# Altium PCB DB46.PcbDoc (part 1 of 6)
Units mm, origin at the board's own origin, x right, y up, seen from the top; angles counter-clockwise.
Board outline 82.2 x 113.2 mm, 8 copper layers (Top Layer, MidLayer1, MidLayer2, GND, MidLayer3, VCC, MidLayer4, Bottom Layer), stack 1.576 mm thick; 186 components, 477 nets, 1727 pads, 1538 vias.
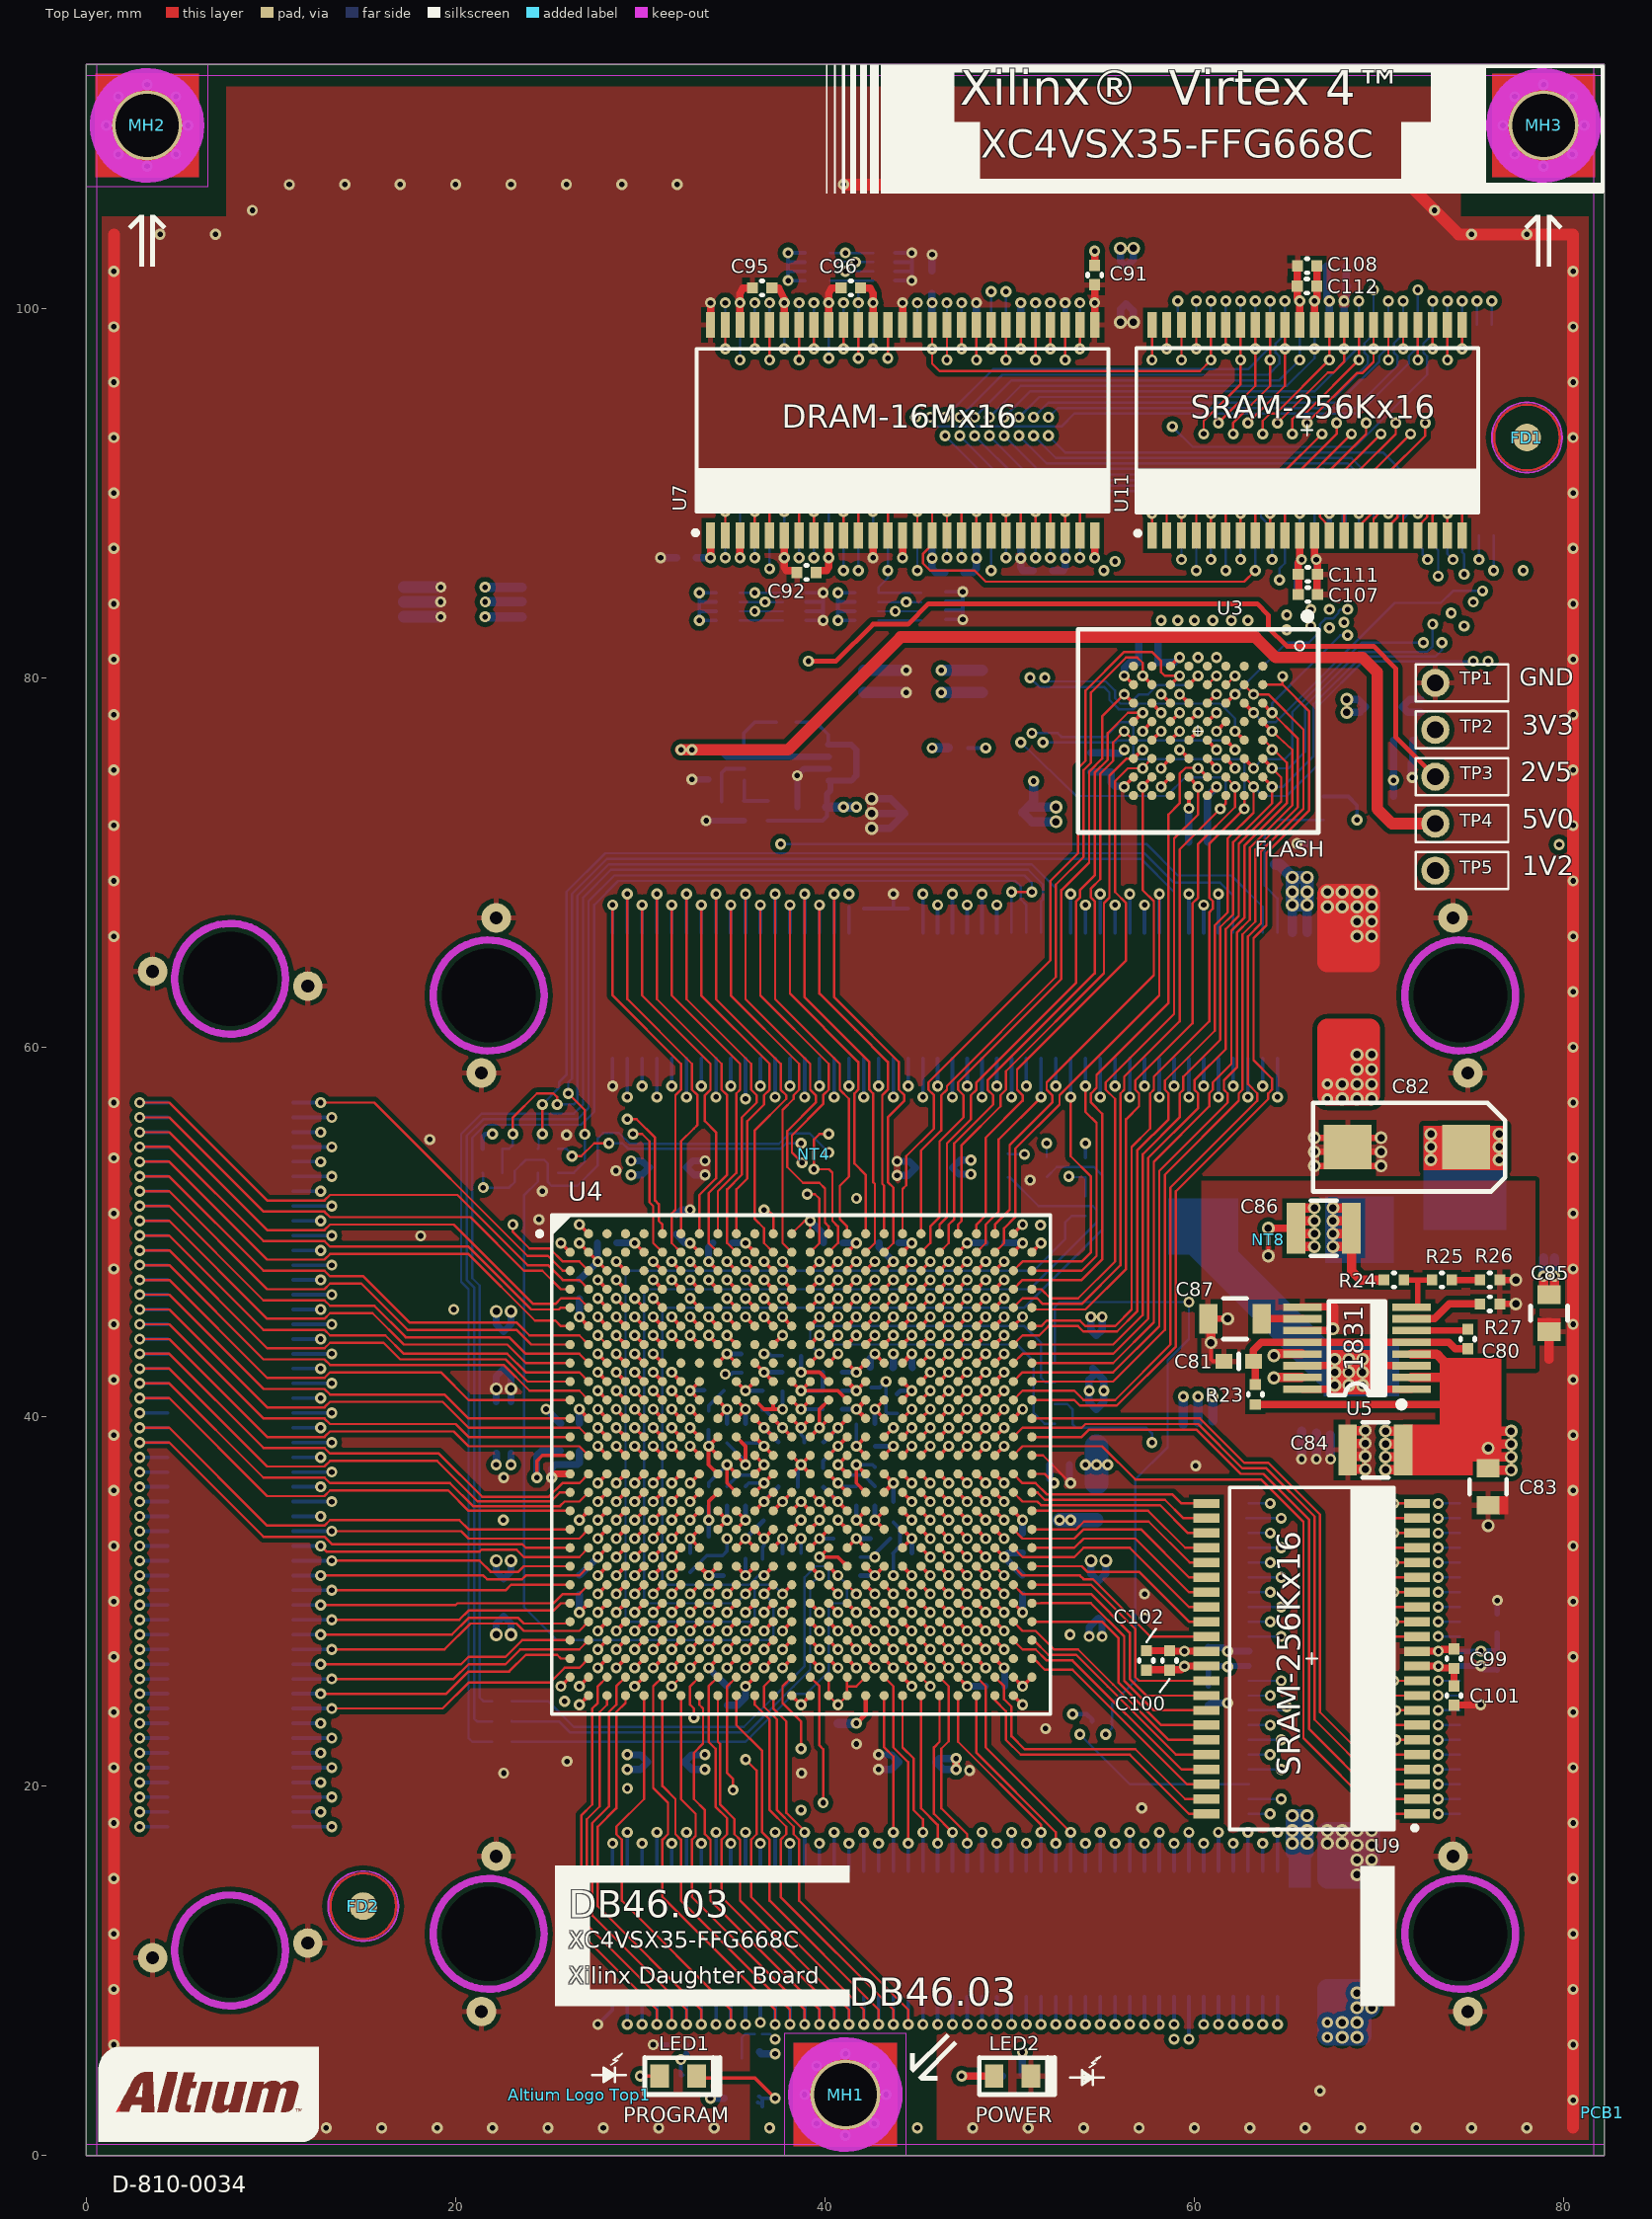
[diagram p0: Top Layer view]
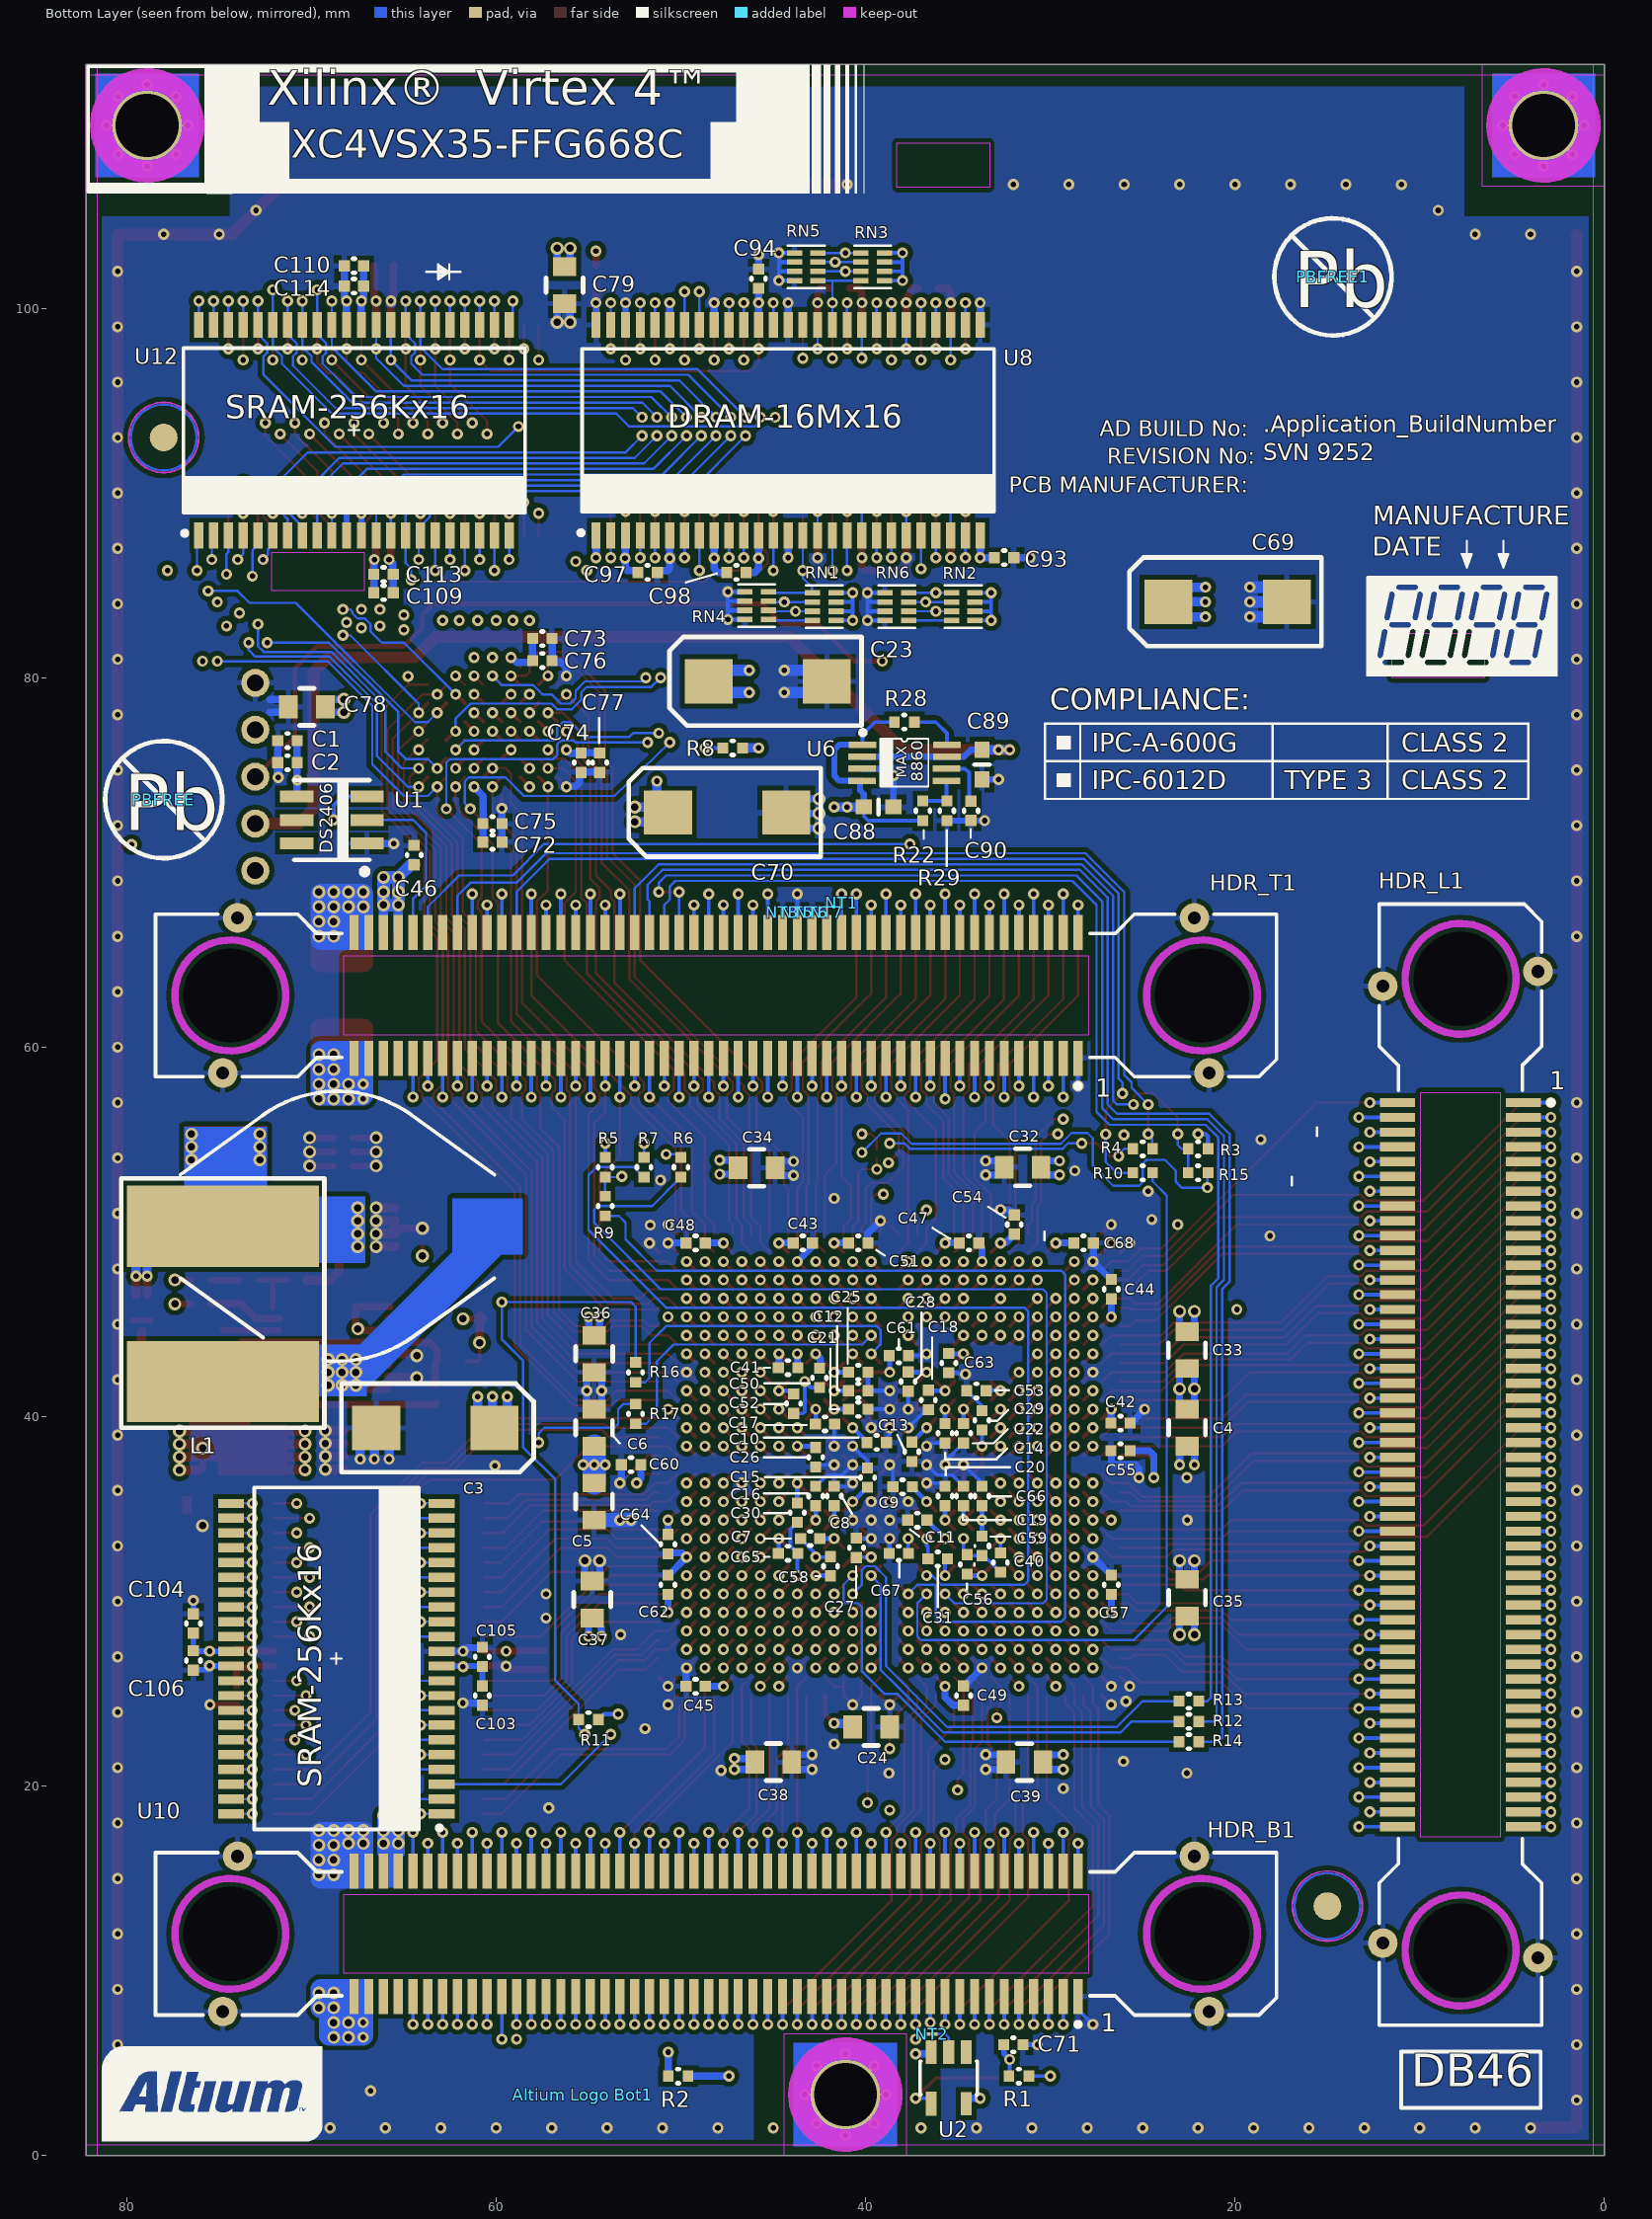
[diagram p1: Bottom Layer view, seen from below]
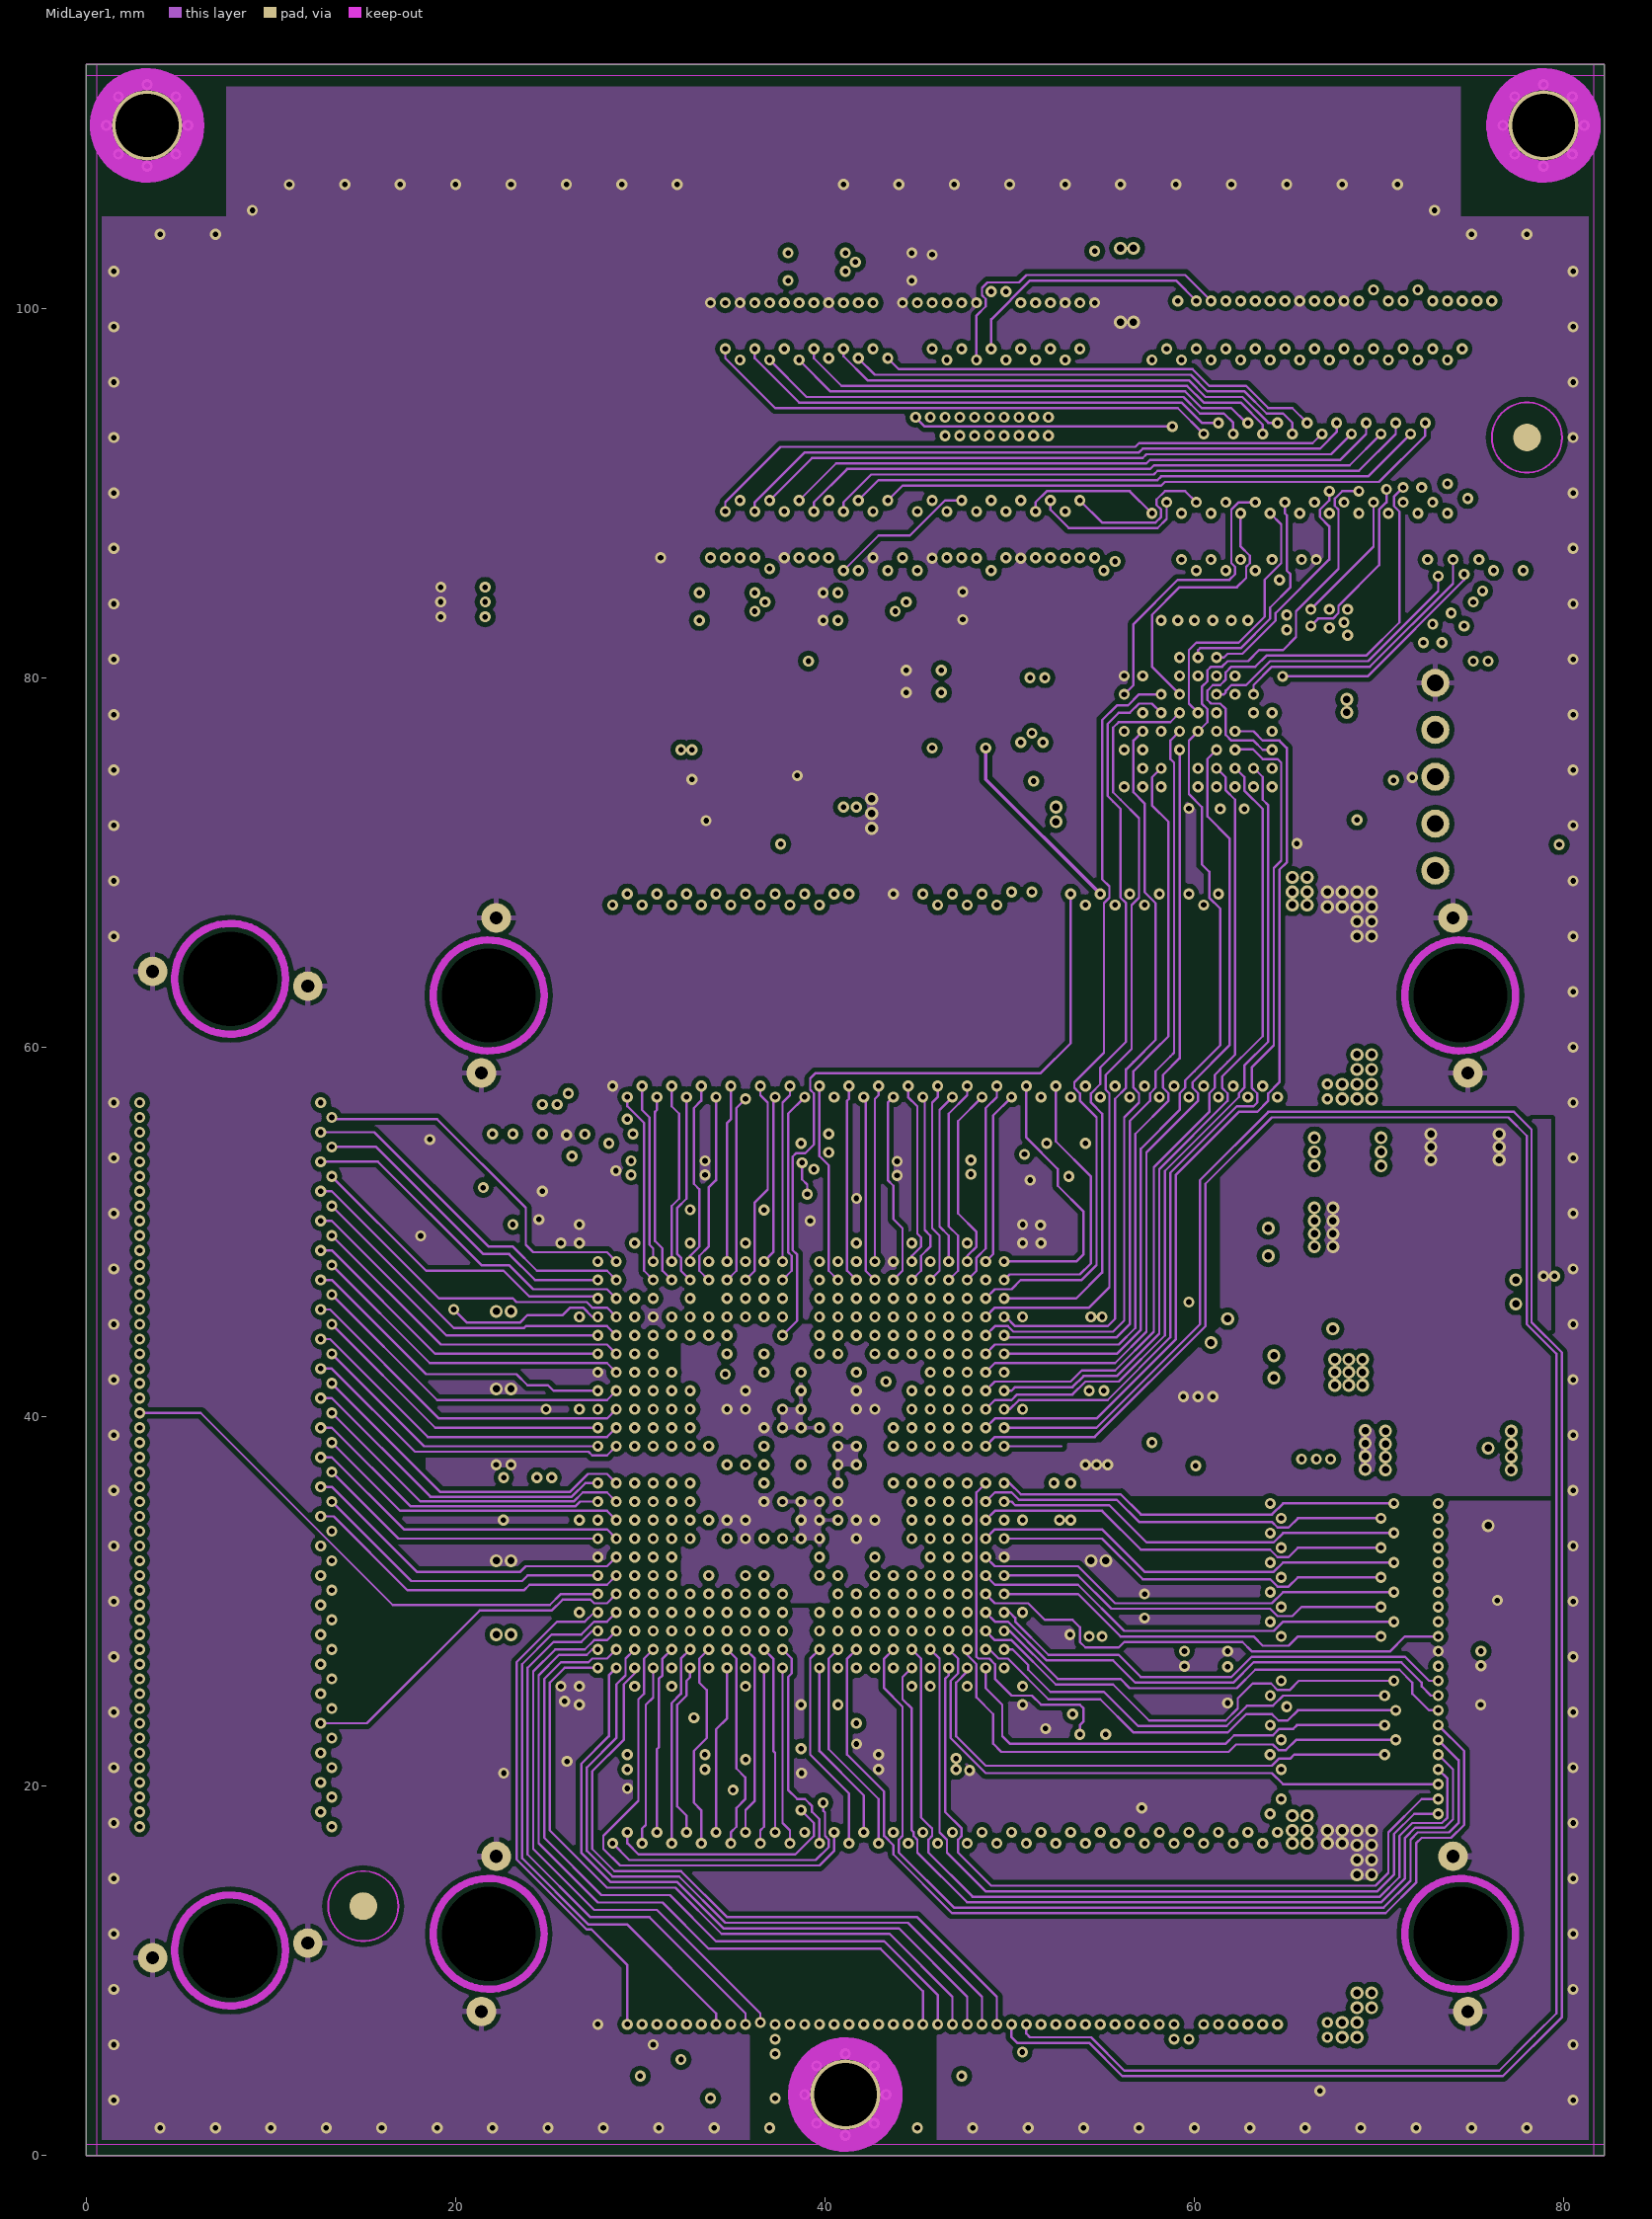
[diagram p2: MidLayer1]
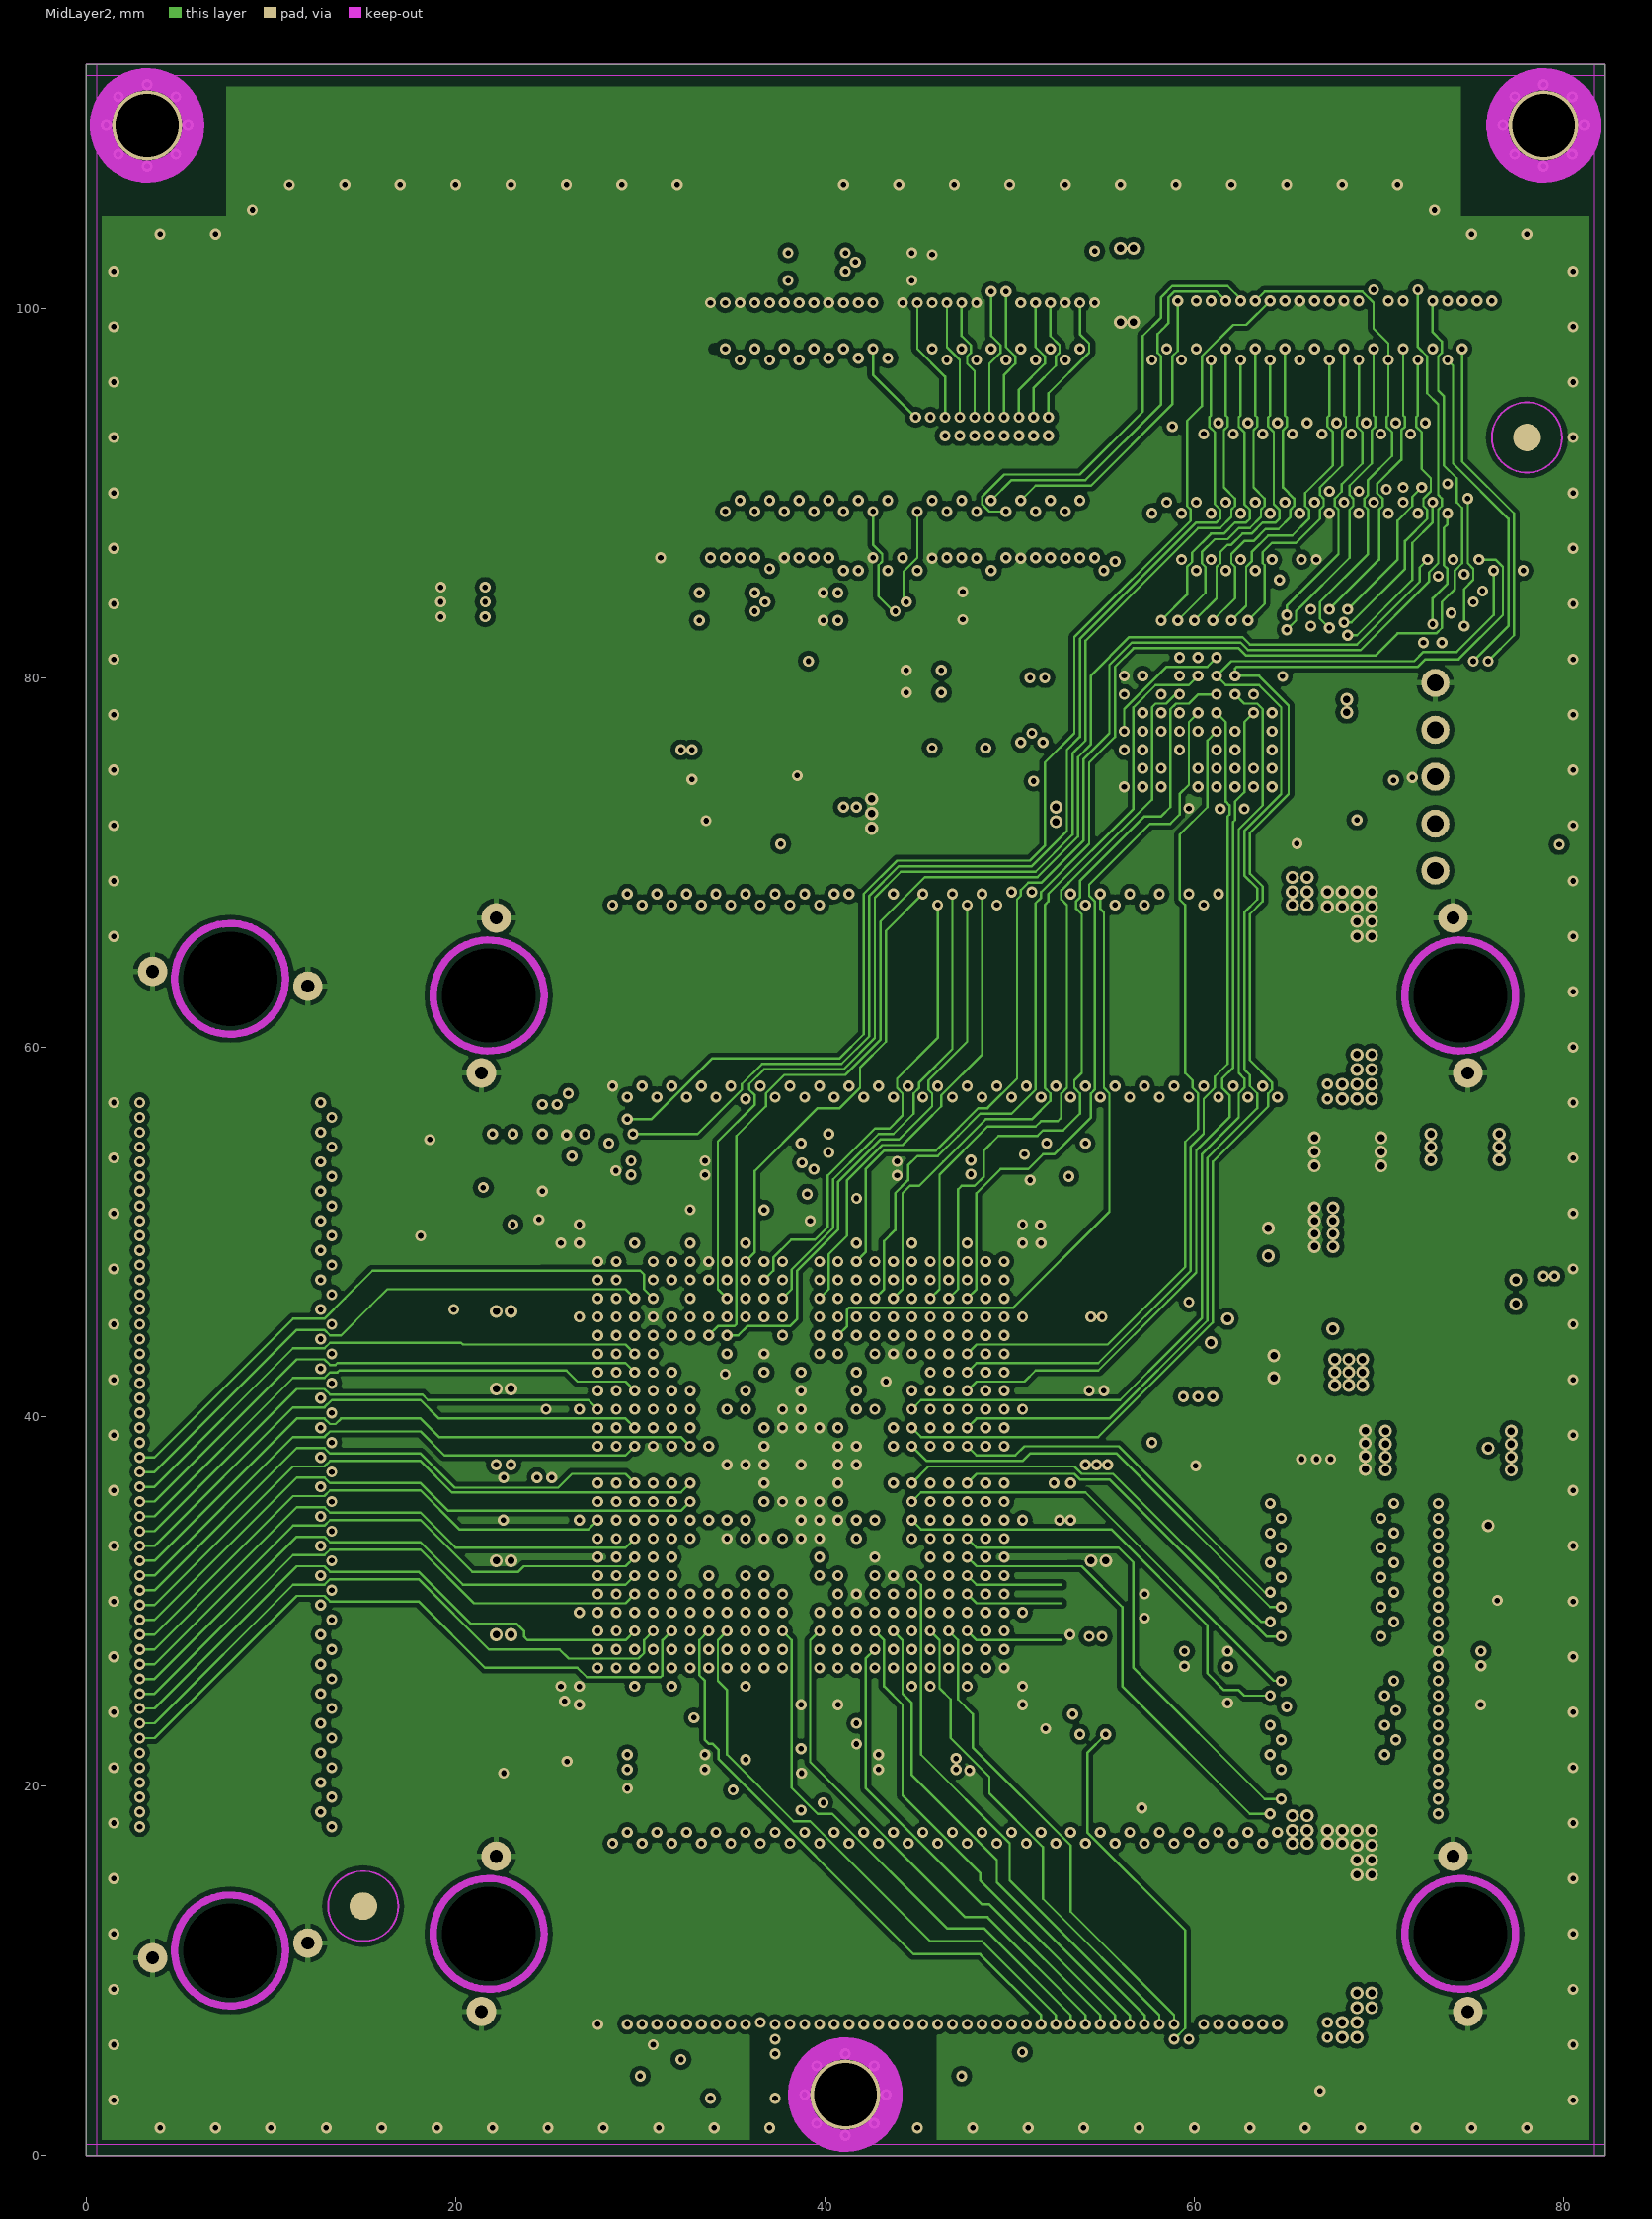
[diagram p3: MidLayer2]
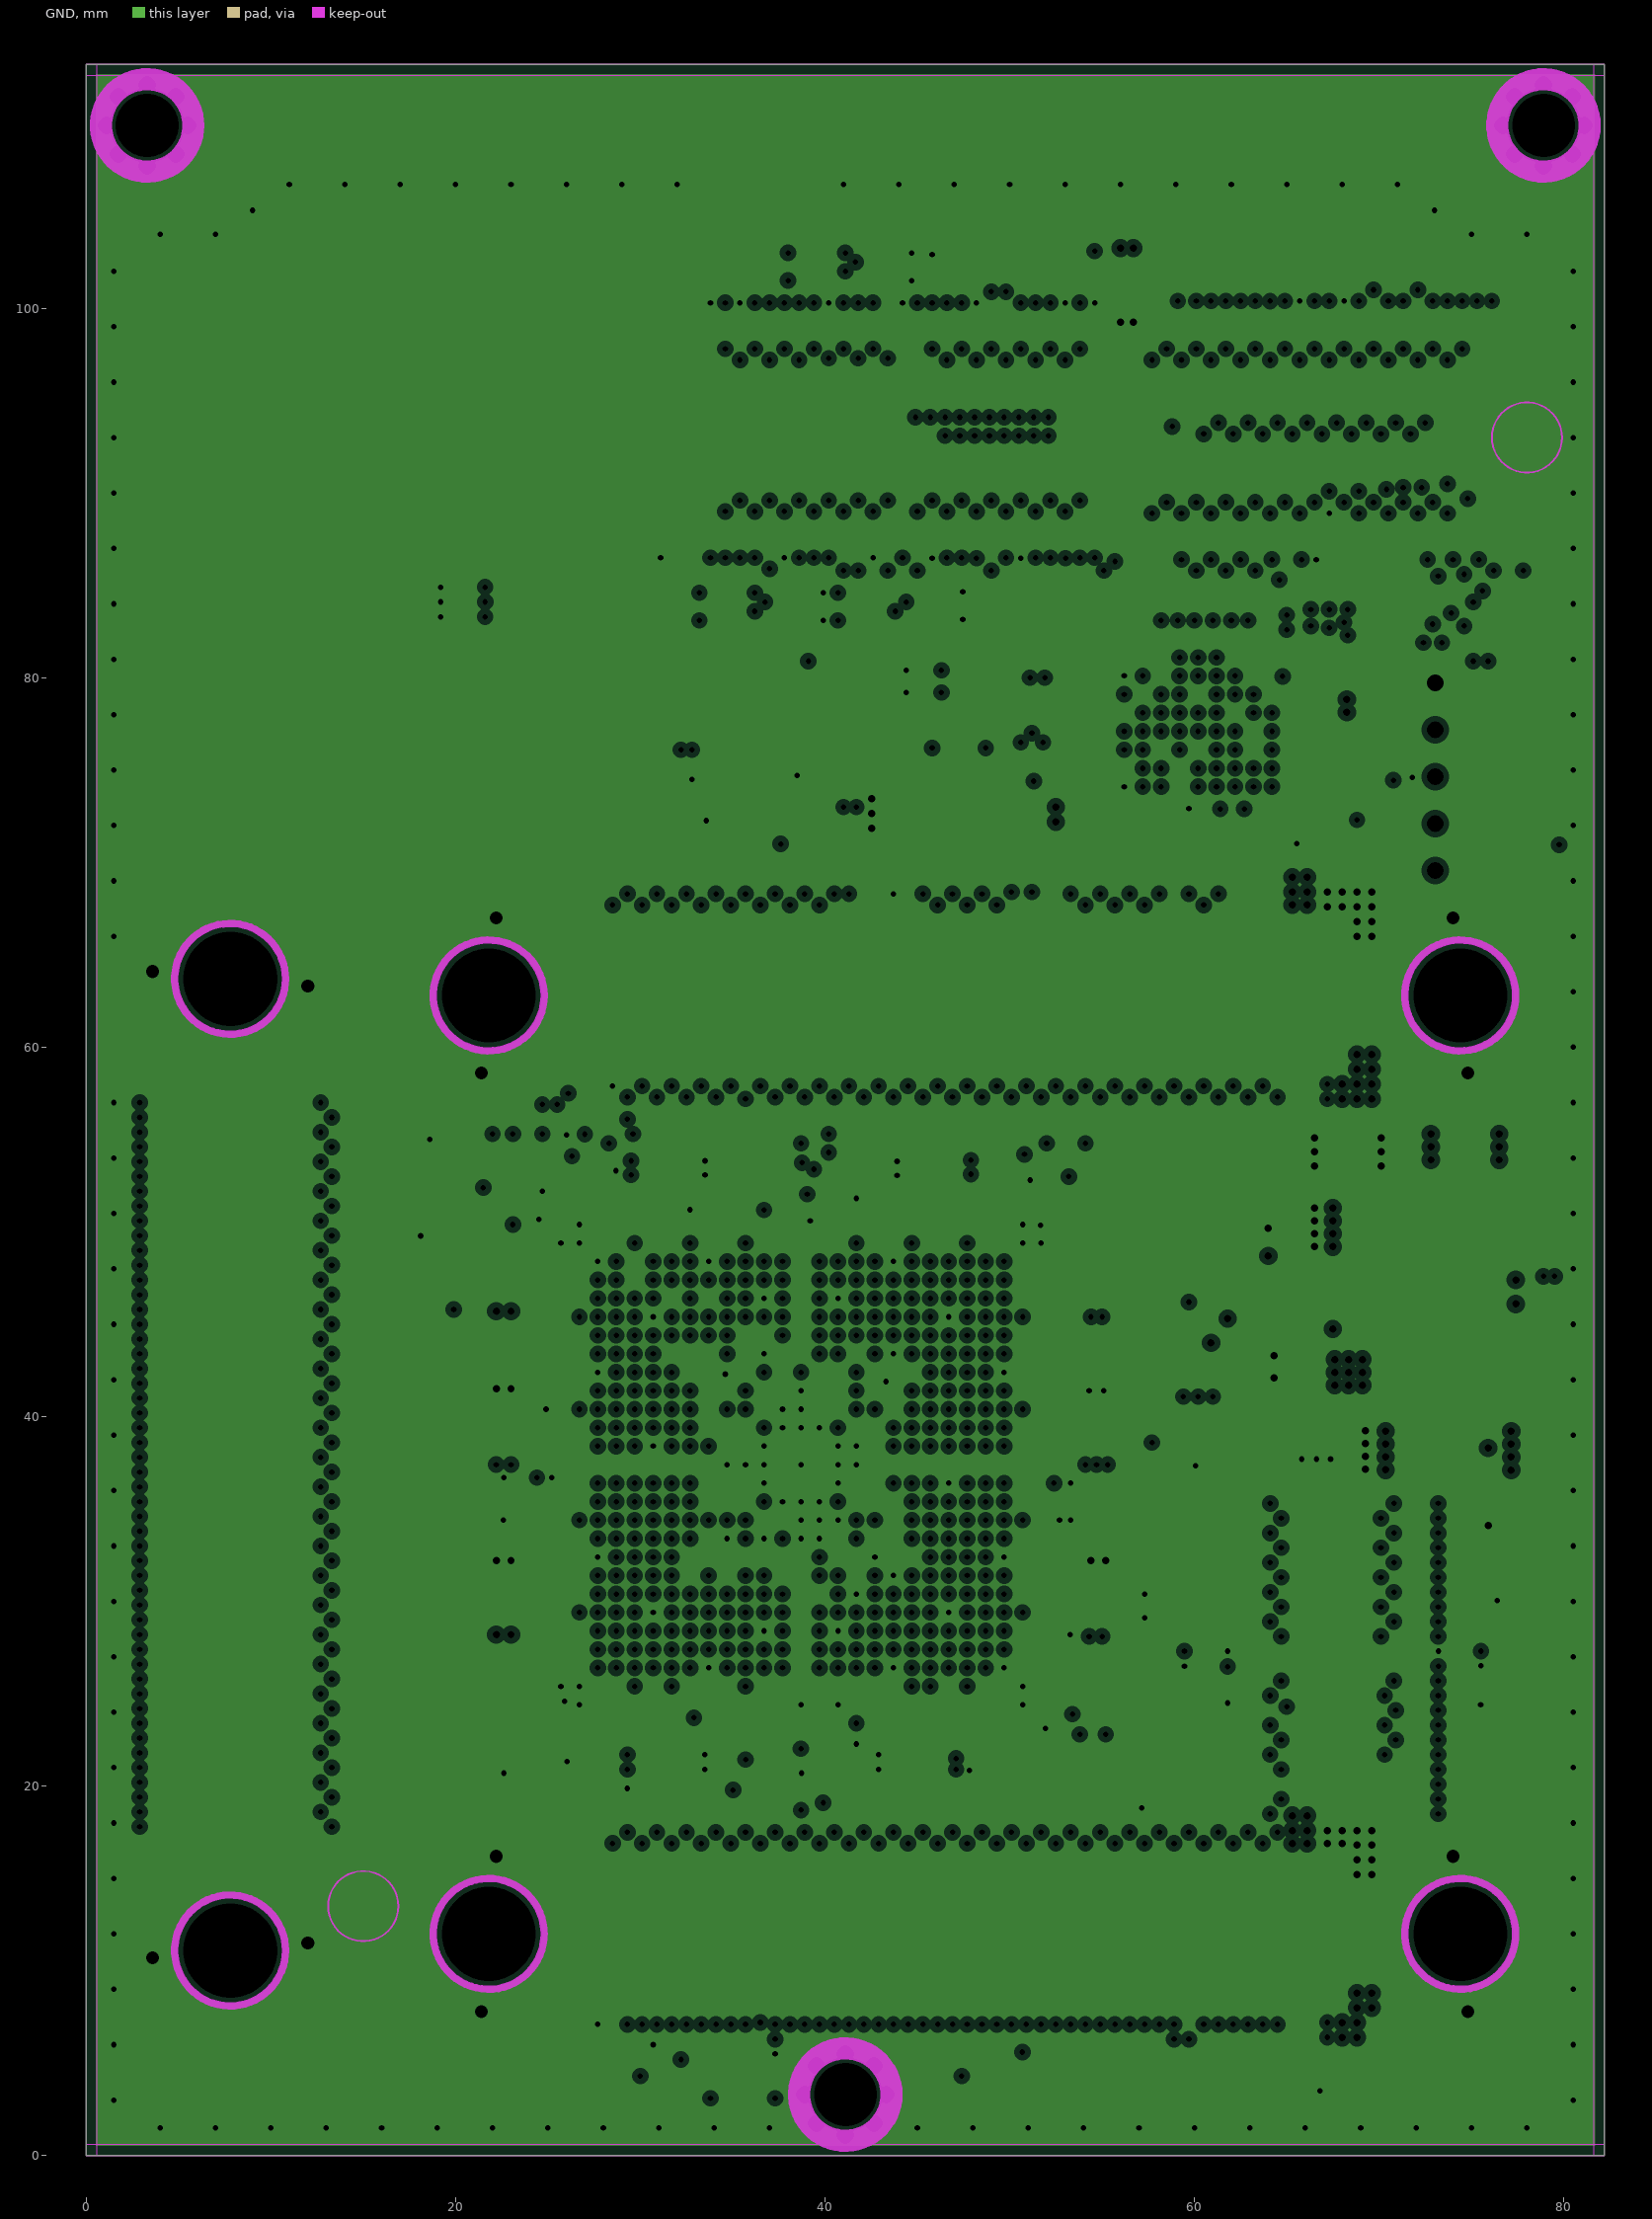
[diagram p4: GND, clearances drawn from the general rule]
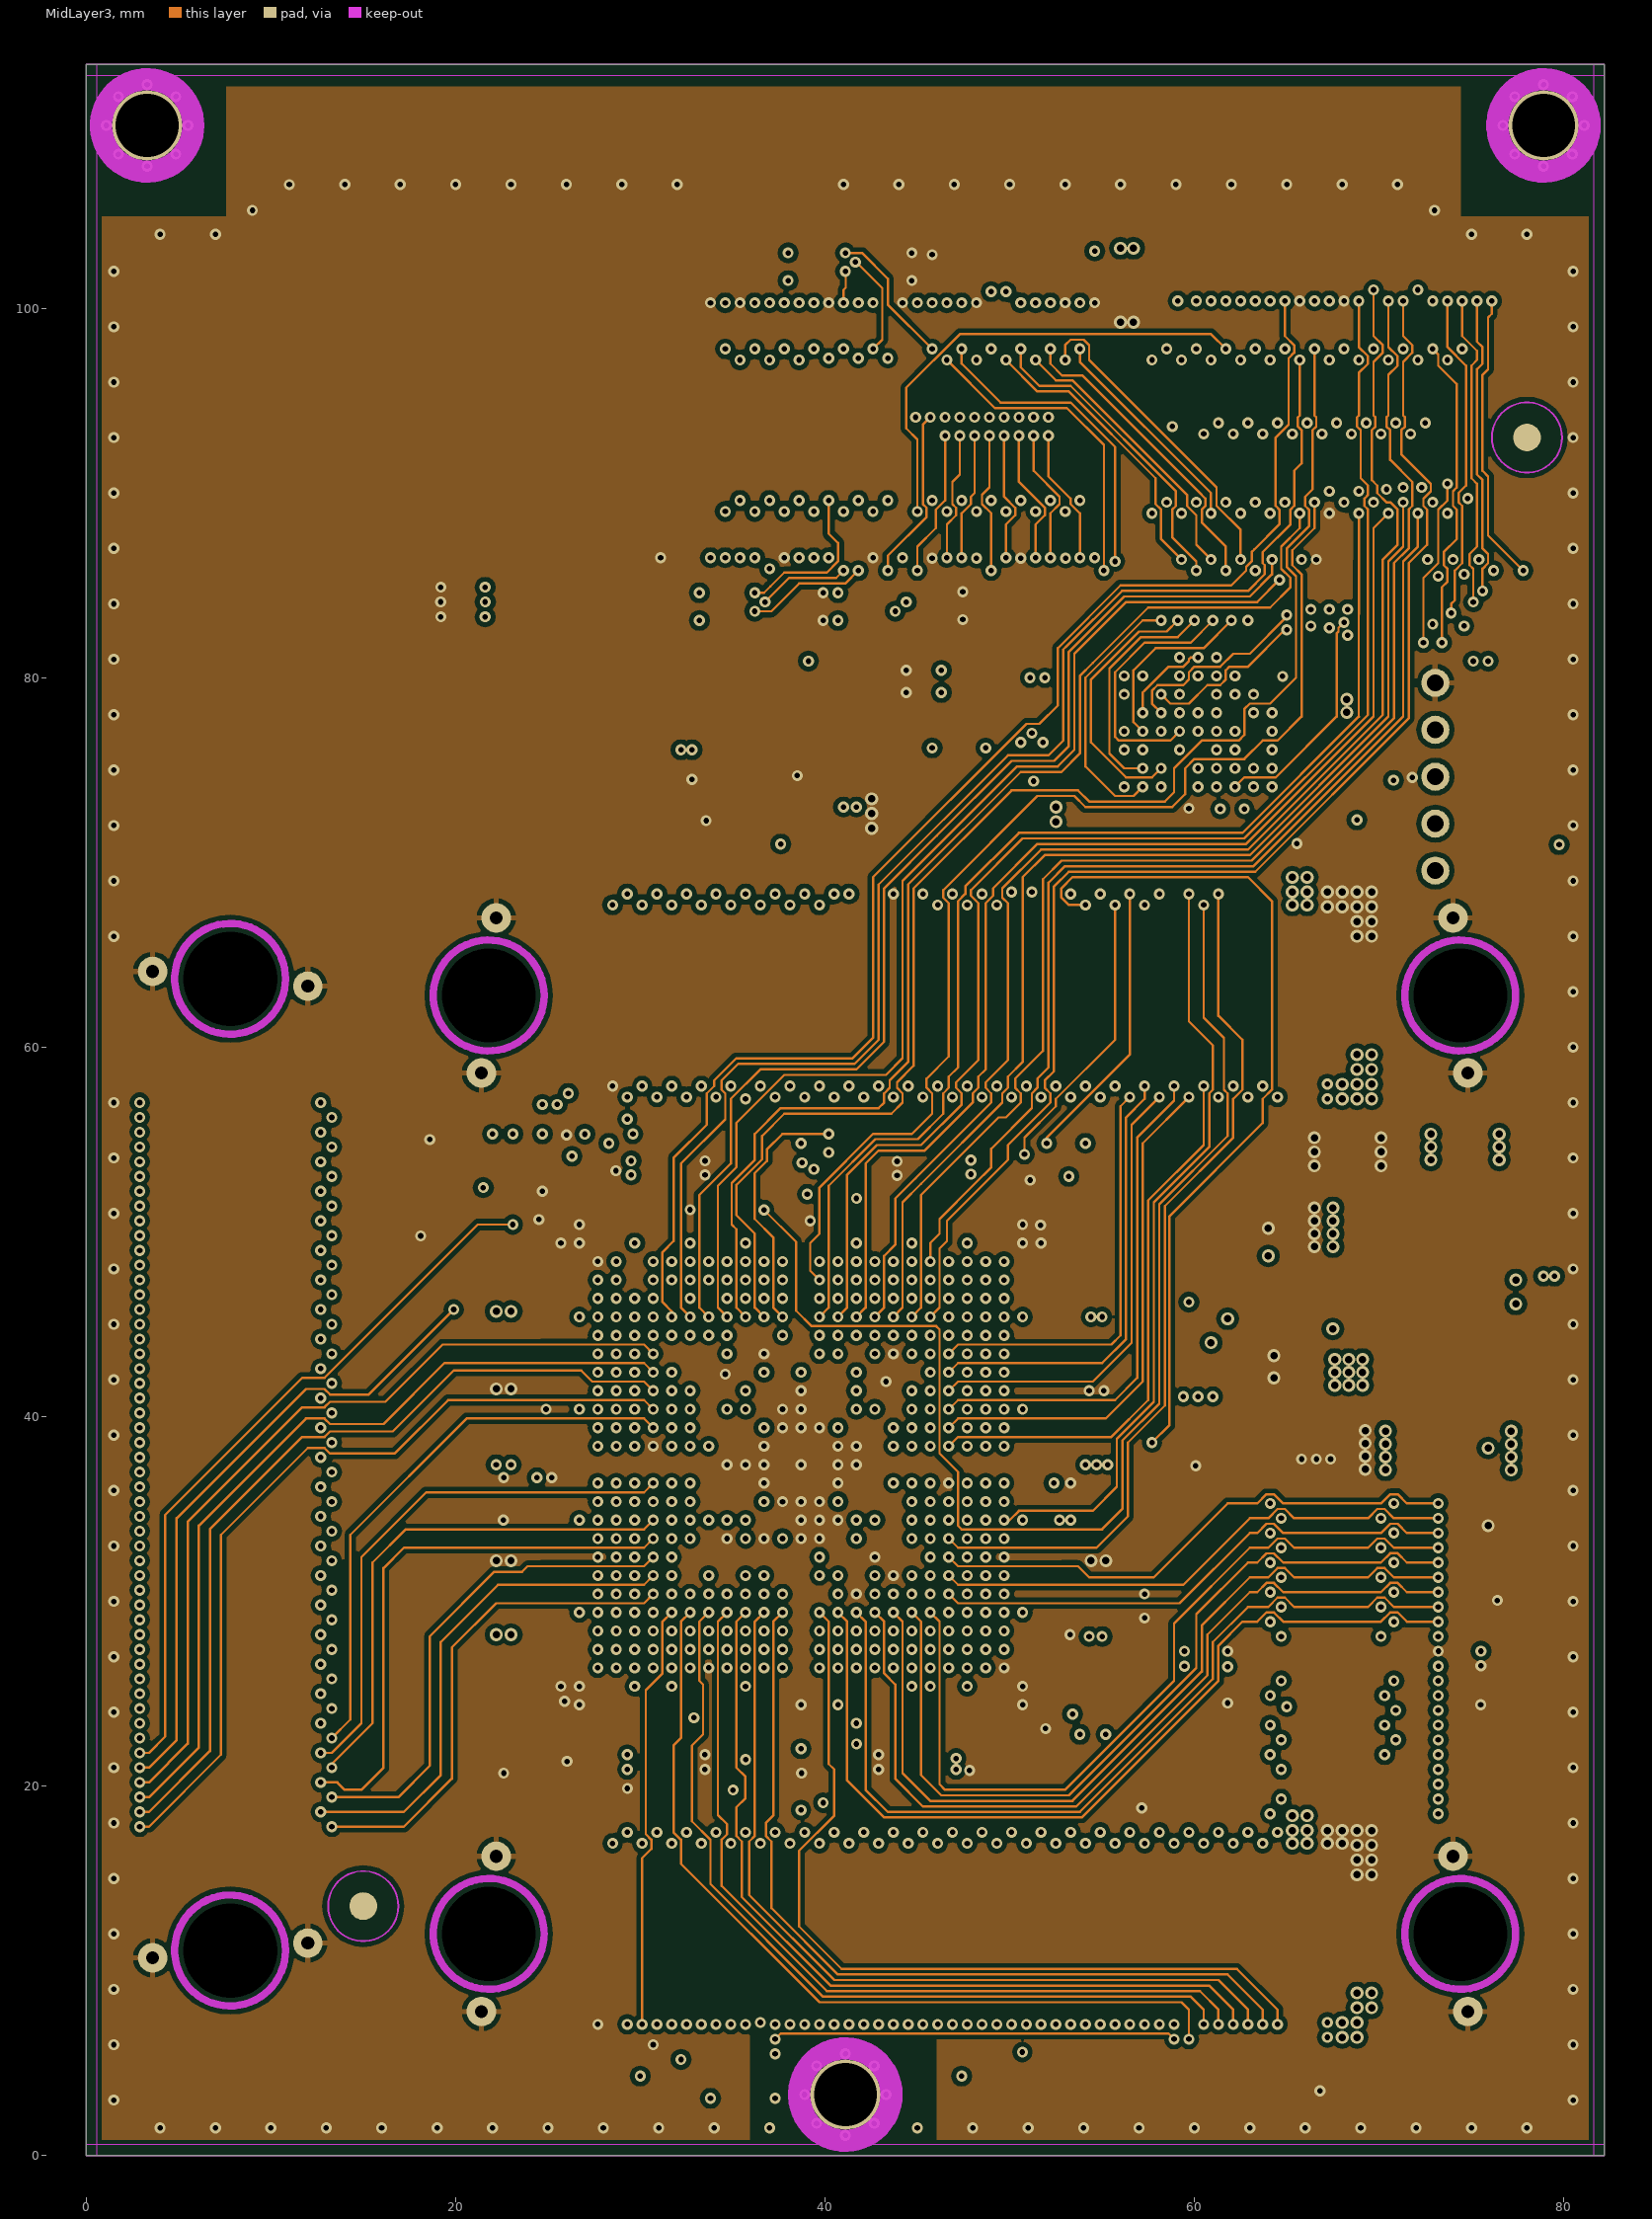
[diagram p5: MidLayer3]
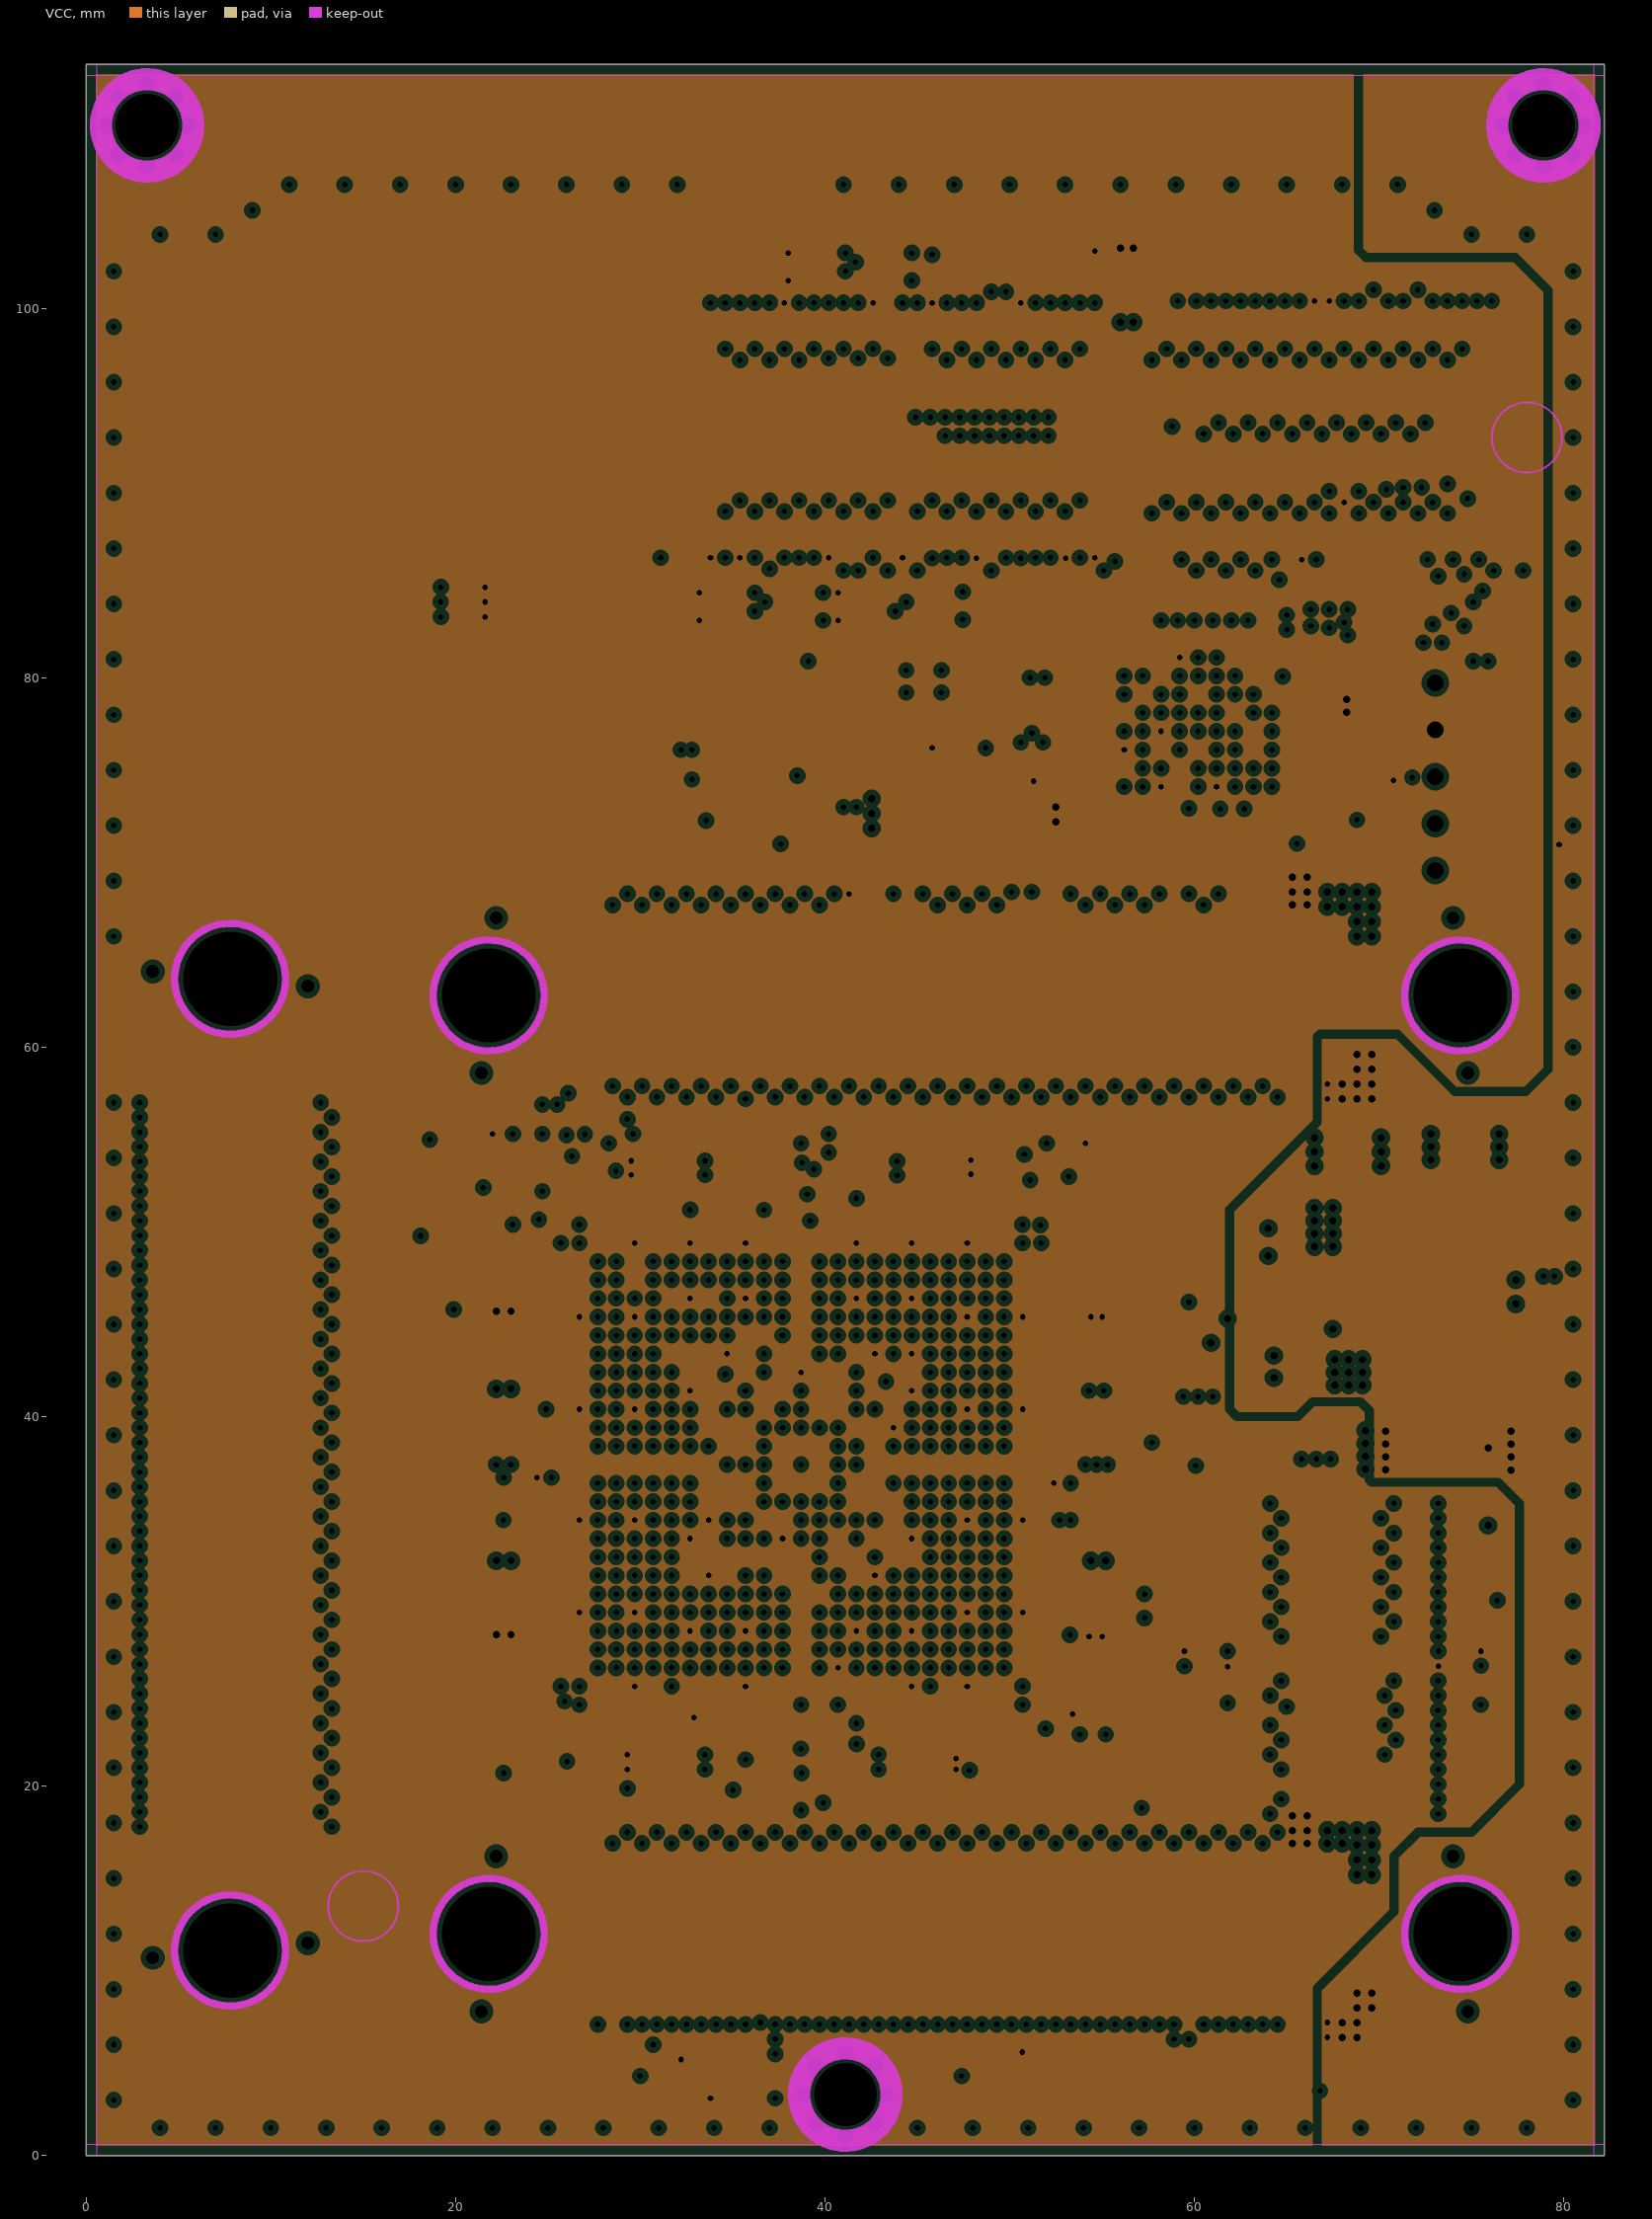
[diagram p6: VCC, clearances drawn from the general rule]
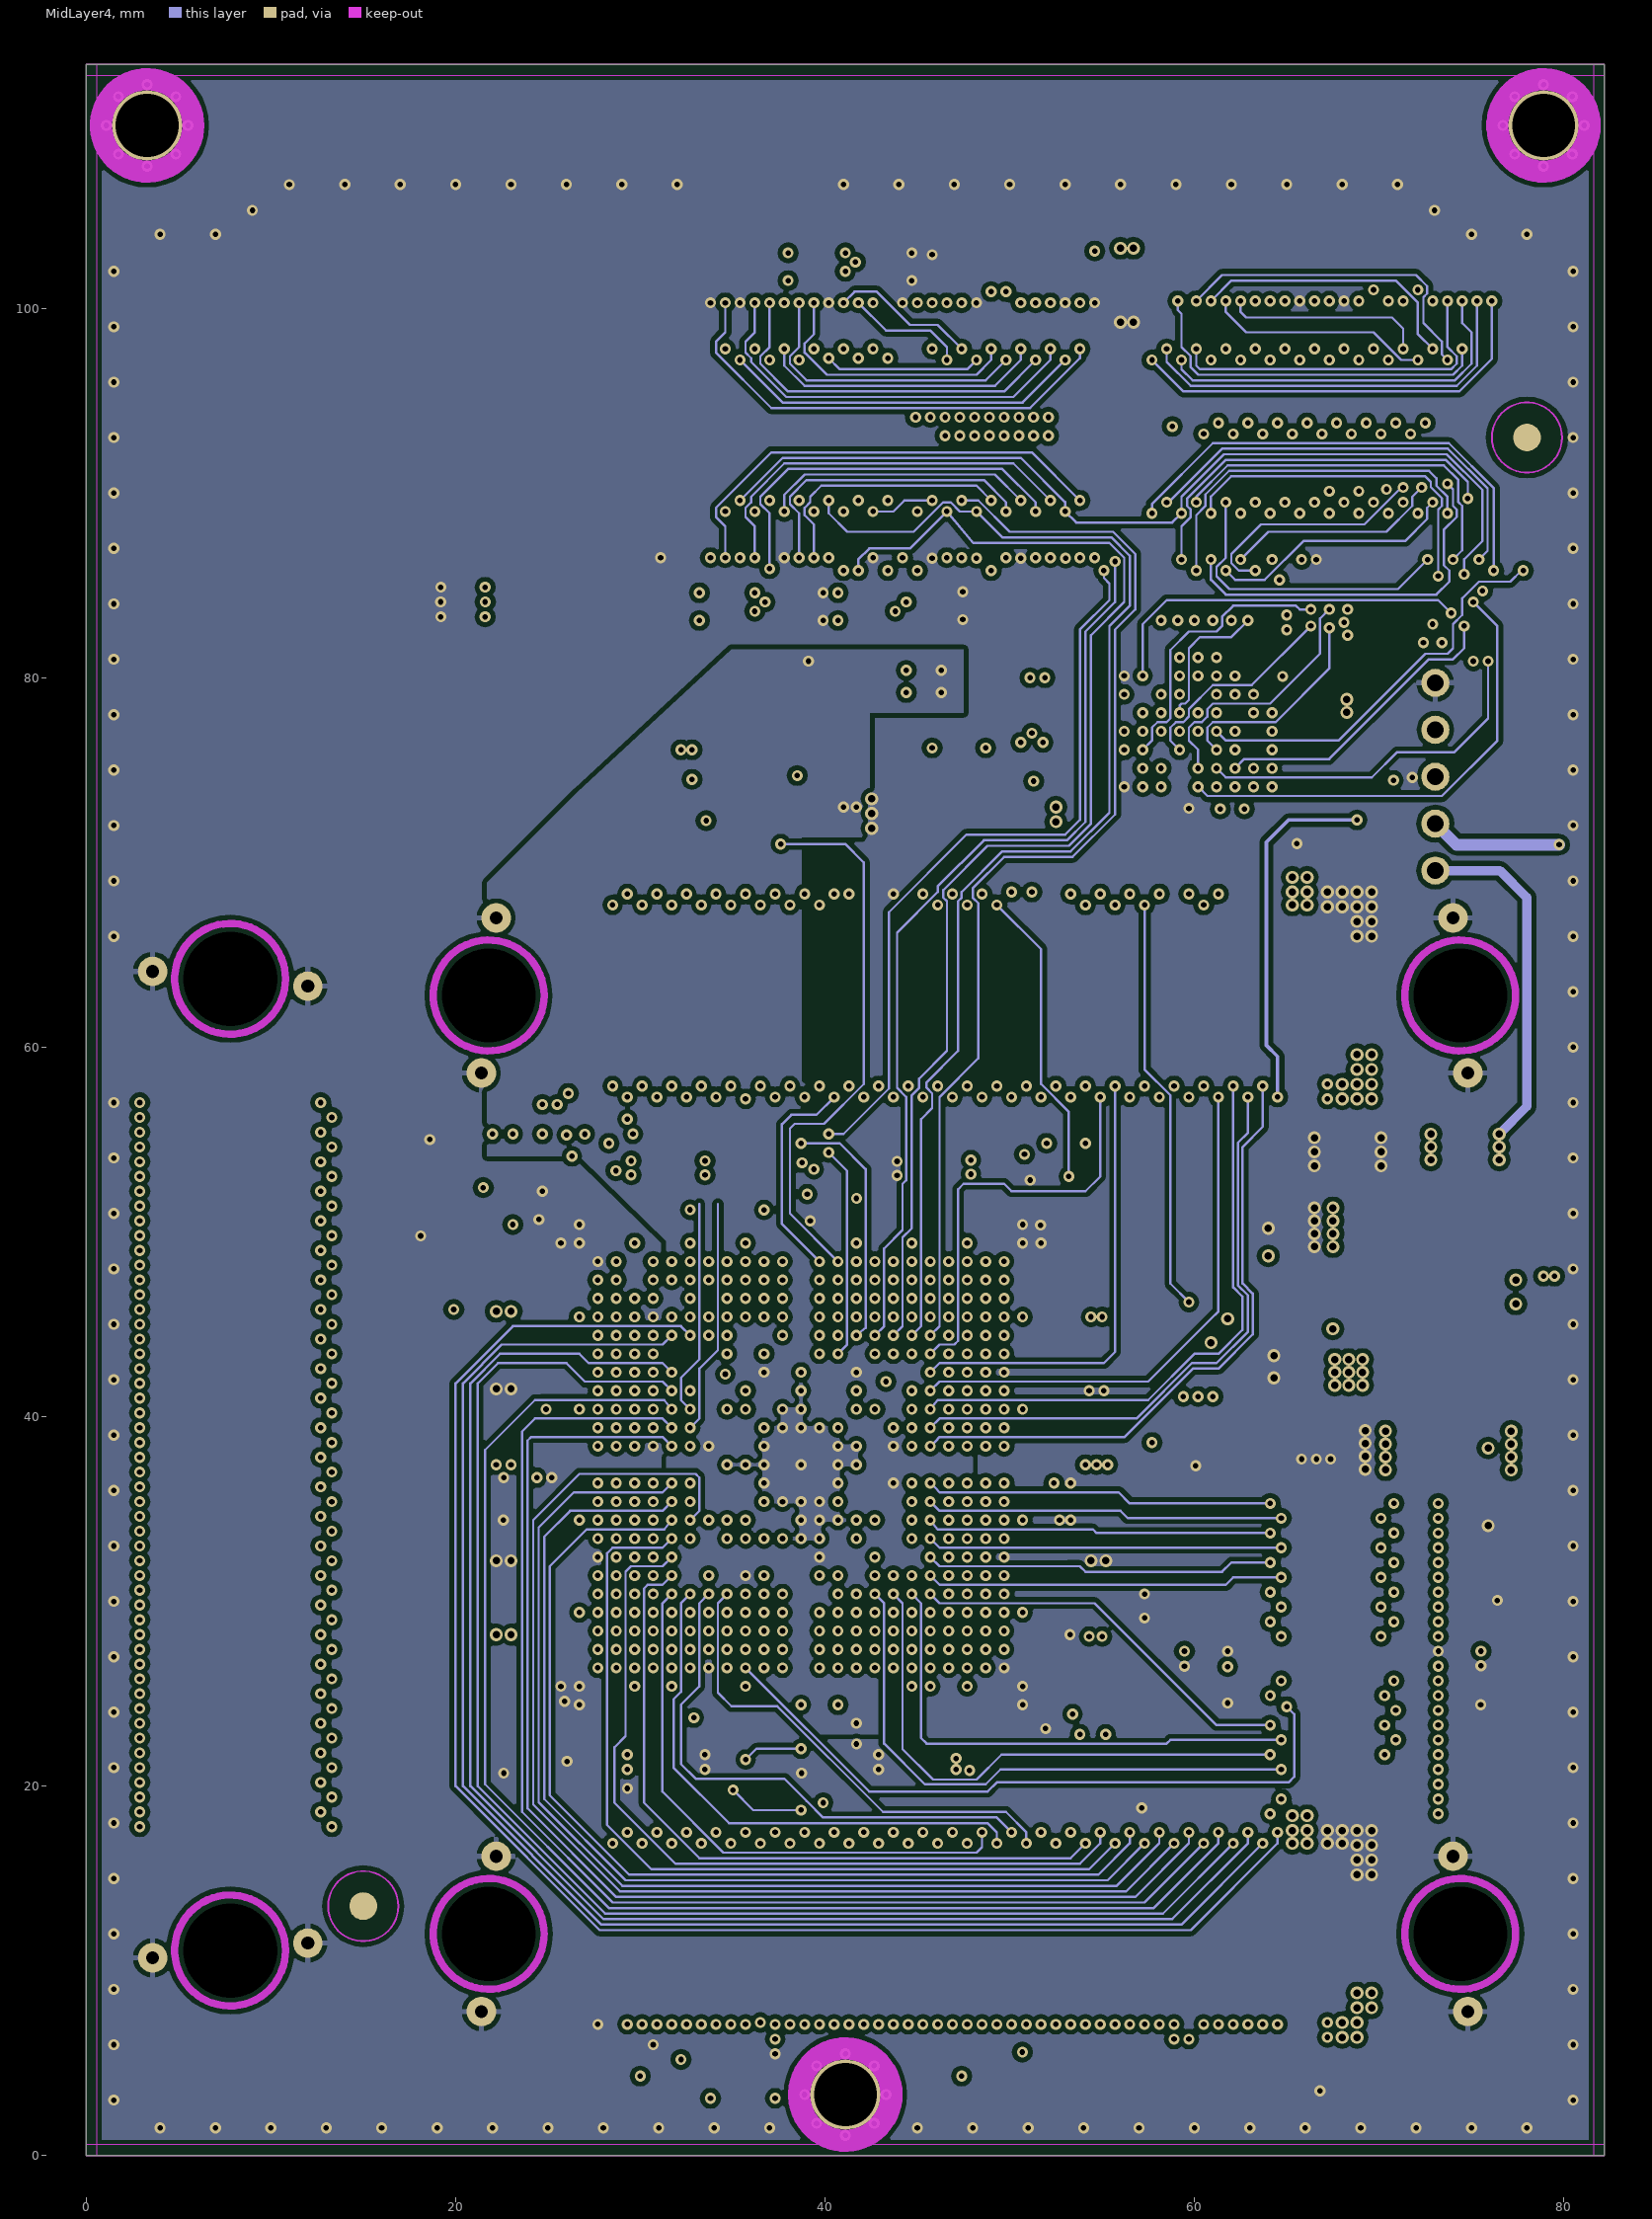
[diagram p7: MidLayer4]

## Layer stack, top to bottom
Top Layer: signal copper 0.0432
Dielectric: prepreg 0.127, FR-4, Dk 4.2
MidLayer1: signal copper 0.0356
Dielectric: core 0.254, FR-4, Dk 4.2
MidLayer2: signal copper 0.0356
Dielectric: prepreg 0.133, FR-4, Dk 4.2
GND: plane copper 0.036, net GND
Dielectric: core 0.254, FR-4, Dk 4.2
MidLayer3: signal copper 0.0356
Dielectric: prepreg 0.127, FR-4, Dk 4.2
VCC: plane copper 0.0356, net (Multiple Nets)
Dielectric: core 0.254, FR-4, Dk 4.2
MidLayer4: signal copper 0.0356
Dielectric: prepreg 0.127, FR-4, Dk 4.2
Bottom Layer: signal copper 0.0432

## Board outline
0,0 0,113.2 38.7,113.2 82.2,113.2 82.2,0

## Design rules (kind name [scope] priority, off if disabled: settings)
Clearance Clearance_Poly_Tight [InNamedPolygon('FPGAPWR-BL-1V2') Or InNamedPolygon('FPGAPWR-BL-3V3') Or InNamedPolygon('FPGAPWR-BL-2V5A') Or InNamedPolygon('FPGAPWR-BL-2V5B') Or InNamedPolygon('FPGAPWR-BL-2V5C') Or InNamedPolygon('FPGAPWR-BL-2V5D') Or InNamedPolygon('FPGAPWR-ML1-1V2') Or InNamedPolygon('FPGAPWR-BL-2V5E') Or InNamedPolygon('1V2-CONNECT-TO-L1-C17' ) Or InNamedPolygon('2V5') Or InNamedPolygon('LX') Or InNamedPolygon('2V5-TOP-CAP') Or InNamedPolygon('AGND-TOP')] p1: gap=0.127
Clearance Clearance_Polygon [InPolygon] p2: gap=0.254
Clearance "Pad-Pad Clearance Same Net" [IsPad vs IsPad] p3: gap=0.127
Clearance "General Clearance" [All] p4: gap=0.127
ComponentClearance [All] p1 off: gap=0.2 collisioncheckmode=3 verticalgap=0.254 showdistances=FALSE
DiffPairsRouting [All] p1 off: maxlimit=0.254 minlimit=0.254 mostfreqgap=0.254 maxuncoupledlength=12.7
FabricationTestPointUsage TestPointUsage [All] p1 off: valid=0 allowmultiple=FALSE
FabricationTestpoint Testpoint [All] p1 off: side=3 testpointundercomponent=TRUE minsize=1.016 maxsize=2.54 preferedsize=1.524 minholesize=0 maxholesize=1.016 preferedholesize=0.813 testpointgrid=0.025 allowsidetop=TRUE allowsidebottom=TRUE usegrid=TRUE gridtolerance=0
HoleSize [All] p1: absolutevalues=TRUE maxlimit=5.2 minlimit=0 maxpercent=80.000 minpercent=20.000
MatchedLengths DiffPair_MatchedLengths [(IsDifferentialPair And (Name = 'HDMI_D0')) Or (IsDifferentialPair And (Name = 'HDMI_D1')) Or (IsDifferentialPair And (Name = 'HDMI_D2')) Or (IsDifferentialPair And (Name = 'HDMI_CLK'))] p1: tolerance=25.4 checknetsindiffpair=TRUE checkdiffpairvsdiffpair=TRUE checkothers=TRUE
MatchedLengths DiffPair_MatchedLengths_1 [(IsDifferentialPair And (Name = 'DIFF_RX1'))] p2: tolerance=25.4 checknetsindiffpair=TRUE checkdiffpairvsdiffpair=TRUE checkothers=TRUE
MinimumAnnularRing MinimumAnnularRing_NonPlated [(ObjectKind = 'Pad') And (HoleDiameter >= '0.7') And (PadIsPlated = 'False')] p1: minimumring=-5
MinimumAnnularRing [All] p2: minimumring=0.15
MinimumSolderMaskSliver [All] p1: minsoldermaskwidth=0.102
PlaneClearance [All] p1: clearance=0.3
PlaneConnect [All] p1: planeconnectstyle=Direct reliefexpansion=0.5 reliefentries=4 reliefconductorwidth=0.25 reliefairgap=0.25
PolygonConnect PolygonConnect_Via [IsVia] p1: connectstyle=Direct reliefconductorwidth=0.254 reliefentries=4 polygonreliefangle="90 Angle"
PolygonConnect "PolygonConnect - Heatsink" [(HasFootprint('TO-263') AND InNet('VCCINT'))] p2: connectstyle=Direct reliefconductorwidth=0.254 reliefentries=4 polygonreliefangle="90 Angle"
PolygonConnect [All] p3: connectstyle=Relief reliefconductorwidth=0.3 reliefentries=4 polygonreliefangle="90 Angle"
RoutingLayers [All] p1: top layer_v5=FALSE mid layer 1_v5=FALSE mid layer 2_v5=FALSE mid layer 3_v5=FALSE mid layer 4_v5=FALSE bottom layer_v5=FALSE
RoutingVias [All] p1: holewidth=0.3 width=0.6 viastyle="Through Hole" minholewidth=0.3 minwidth=0.6 maxholewidth=0.5 maxwidth=0.9
ShortCircuit ShortCircuit_1 [Net = 'No Net' vs Net = 'No Net'] p1: allowed=TRUE
ShortCircuit [All] p2: allowed=FALSE
SilkToSilkClearance SilkToSilkClearance_InvToFill [(ObjectKind = 'Text') And (TextKind <> 'Stroke Font') vs isFill] p1: silktosilkclearance=0
SilkToSilkClearance SilkToSilkClearance_Labels [(ObjectKind = 'Text') And (TextKind <> 'Stroke Font') vs (ObjectKind = 'Text') And (TextKind <> 'Stroke Font')] p2: silktosilkclearance=0
SilkToSilkClearance SilkToSilkClearance_Pb [(ObjectKind = 'Text') And (StringText = 'Pb') vs istrack and onsilkscreen] p3: silktosilkclearance=0
SilkToSilkClearance [All] p4: silktosilkclearance=0.127
SilkscreenOverComponentPads [All] p1: minsilkscreentomaskgap=0.051
SolderMaskExpansion SolderMaskExpansion_Vias [IsVia] p1: expansion=-0.65
SolderMaskExpansion [All] p2: expansion=0.038
Width [All] p1: maxlimit=2.5 minlimit=0.127 preferedwidth=0.127
16 further rules are at their usual default settings.

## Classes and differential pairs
component class U_DB46_Hardware_Kit: FD1 FD2 PCB1
channel class SRAM_256Kx16_TSOP44: U_SRAM_K6R4016V1D-TC10T_256Kx161 U_SRAM_K6R4016V1D-TC10T_256Kx162
component class COM_SRAM: C107 C108 C109 C110 C111 C112 C113 C114 U11 U12
component class U_FPGA: C78 C79 NT2 NT3 NT4 NT5 NT6 NT7 R3 R4 R5 R6 R7 R8 R9 R10 R11 R12 R13 R14 R15 R16 R17 U4
component class COM_SDRAM: C91 C92 C93 C94 C95 C96 C97 C98 U7 U8
component class U_CommonMemory_Termination: RN1 RN2 RN3 RN4 RN5 RN6
component class COM_FLASH: C72 C73 C74 C75 C76 C77 U3
component class U_MOUNTS: "Altium Logo Bot1" "Altium Logo Top1" LB1 LB2 LB3 MH1 MH2 MH3 PCBA1
net class PWRNET: 1V2 2V5 3V3 5V0 AGND
differential pair class DIFF_OUT: DIFF_TX0 DIFF_TX1 DIFF_TX2 DIFF_TX3
differential pair class DIFF_IN: DIFF_RX0 DIFF_RX1 DIFF_RX2 DIFF_RX3
net class SW[4..0]: SW0 SW1 SW2 SW3 SW4
net class LED[7..0]: LED0 LED1 LED2 LED3 LED4 LED5 LED6 LED7
net class IO[35..0]: IO0 IO1 IO2 IO3 IO4 IO5 IO6 IO7 IO8 IO9 IO10 IO11 IO12 IO13 IO14 IO15 IO16 IO17 IO18 IO19 IO20 IO21 IO22 IO23 IO24 IO25 IO26 IO27 IO28 IO29 IO30 IO31 IO32 IO33 IO34 IO35
net class FPGA_M[2..0]: FPGA_M0 FPGA_M1 FPGA_M2
net class FPGA_ID[3..0]: FPGA_ID0 FPGA_ID1 FPGA_ID2 FPGA_ID3
net class DIP[7..0]: DIP0 DIP1 DIP2 DIP3 DIP4 DIP5 DIP6 DIP7
net class BUS_NBE[3..0]: BUS_NBE0 BUS_NBE1 BUS_NBE2 BUS_NBE3
net class BUS_D[31..0]: BUS_D0 BUS_D1 BUS_D2 BUS_D3 BUS_D4 BUS_D5 BUS_D6 BUS_D7 BUS_D8 BUS_D9 BUS_D10 BUS_D11 BUS_D12 BUS_D13 BUS_D14 BUS_D15 BUS_D16 BUS_D17 BUS_D18 BUS_D19 BUS_D20 BUS_D21 BUS_D22 BUS_D23 BUS_D24 BUS_D25 BUS_D26 BUS_D27 BUS_D28 BUS_D29 BUS_D30 BUS_D31
component class U_MotherBoardConnectors: HDR_B1 HDR_L HDR_L1 HDR_T1 NT1
component class U_Bypass_1V2: C3 C4 C5 C6 C7 C8 C9 C10 C11 C12 C13 C14 C15 C16 C17 C18 C19 C20 C21 C22
component class U_Bypass_3V3: C32 C33 C34 C35 C36 C37 C38 C39 C40 C41 C42 C43 C44 C45 C46 C46_FP C47 C47_FP C48 C48_FP C49 C49_FP C50 C51 C51_FP C52 C52_FP C53 C54 C55 C56 C56_FP C57 C58 C58_FP C59 C59_FP C60 C60_FP C61 C61_FP C62 C63 C64 C65 C65_FP C66 C67 C68 C69_FP C71_FP C72_FP C73_FP C79_FP C81_FP C82_FP C88_FP C90_FP C91_FP C93_FP C95_FP C96_FP C97_FP C98_FP C101_FP C102_FP C103_FP C104_FP C105_FP C106_FP
component class U_Bypass_Board: C1_PSU C4_MB C6_MB C69 C70
net class DAU_TFT_BLUE[4..0]: DAU_TFT_BLUE0 DAU_TFT_BLUE1 DAU_TFT_BLUE2 DAU_TFT_BLUE3 DAU_TFT_BLUE4
net class DAU_TFT_CL[3..1]: DAU_TFT_CL1 DAU_TFT_CL2 DAU_TFT_CL3
net class DAU_TFT_GREEN[5..0]: DAU_TFT_GREEN0 DAU_TFT_GREEN1 DAU_TFT_GREEN2 DAU_TFT_GREEN3 DAU_TFT_GREEN4 DAU_TFT_GREEN5
net class DAU_TFT_RED[4..0]: DAU_TFT_RED0 DAU_TFT_RED1 DAU_TFT_RED2 DAU_TFT_RED3 DAU_TFT_RED4
net class EXTEND_A[49..0]: EXTEND_A0 EXTEND_A1 EXTEND_A2 EXTEND_A3 EXTEND_A4 EXTEND_A5 EXTEND_A6 EXTEND_A7 EXTEND_A8 EXTEND_A9 EXTEND_A10 EXTEND_A11 EXTEND_A12 EXTEND_A13 EXTEND_A14 EXTEND_A15 EXTEND_A16 EXTEND_A17 EXTEND_A18 EXTEND_A19 EXTEND_A20 EXTEND_A21 EXTEND_A22 EXTEND_A23 EXTEND_A24 EXTEND_A25 EXTEND_A26 EXTEND_A27 EXTEND_A28 EXTEND_A29 EXTEND_A30 EXTEND_A31 EXTEND_A32 EXTEND_A33 EXTEND_A34 EXTEND_A35 EXTEND_A36 EXTEND_A37 EXTEND_A38 EXTEND_A39 EXTEND_A40 EXTEND_A41 EXTEND_A42 EXTEND_A43 EXTEND_A44 EXTEND_A45 EXTEND_A46 EXTEND_A47 EXTEND_A48 EXTEND_A49
net class EXTEND_B[49..0]: EXTEND_B0 EXTEND_B1 EXTEND_B2 EXTEND_B3 EXTEND_B4 EXTEND_B5 EXTEND_B6 EXTEND_B7 EXTEND_B8 EXTEND_B9 EXTEND_B10 EXTEND_B11 EXTEND_B12 EXTEND_B13 EXTEND_B14 EXTEND_B15 EXTEND_B16 EXTEND_B17 EXTEND_B18 EXTEND_B19 EXTEND_B20 EXTEND_B21 EXTEND_B22 EXTEND_B23 EXTEND_B24 EXTEND_B25 EXTEND_B26 EXTEND_B27 EXTEND_B28 EXTEND_B29 EXTEND_B30 EXTEND_B31 EXTEND_B32 EXTEND_B33 EXTEND_B34 EXTEND_B35 EXTEND_B36 EXTEND_B37 EXTEND_B38 EXTEND_B39 EXTEND_B40 EXTEND_B41 EXTEND_B42 EXTEND_B43 EXTEND_B44 EXTEND_B45 EXTEND_B46 EXTEND_B47 EXTEND_B48 EXTEND_B49
net class EXTEND_C[49..0]: EXTEND_C0 EXTEND_C1 EXTEND_C2 EXTEND_C3 EXTEND_C4 EXTEND_C5 EXTEND_C6 EXTEND_C7 EXTEND_C8 EXTEND_C9 EXTEND_C10 EXTEND_C11 EXTEND_C12 EXTEND_C13 EXTEND_C14 EXTEND_C15 EXTEND_C16 EXTEND_C17 EXTEND_C18 EXTEND_C19 EXTEND_C20 EXTEND_C21 EXTEND_C22 EXTEND_C23 EXTEND_C24 EXTEND_C25 EXTEND_C26 EXTEND_C27 EXTEND_C28 EXTEND_C29 EXTEND_C30 EXTEND_C31 EXTEND_C32 EXTEND_C33 EXTEND_C34 EXTEND_C35 EXTEND_C36 EXTEND_C37 EXTEND_C38 EXTEND_C39 EXTEND_C40 EXTEND_C41 EXTEND_C42 EXTEND_C43 EXTEND_C44 EXTEND_C45 EXTEND_C46 EXTEND_C47 EXTEND_C48 EXTEND_C49
net class SRAM1_A[18..0]: SRAM1_A0 SRAM1_A1 SRAM1_A2 SRAM1_A3 SRAM1_A4 SRAM1_A5 SRAM1_A6 SRAM1_A7 SRAM1_A8 SRAM1_A9 SRAM1_A10 SRAM1_A11 SRAM1_A12 SRAM1_A13 SRAM1_A14 SRAM1_A15 SRAM1_A16 SRAM1_A17 SRAM1_A18
net class SRAM1_D[15..0]: SRAM1_D0 SRAM1_D1 SRAM1_D2 SRAM1_D3 SRAM1_D4 SRAM1_D5 SRAM1_D6 SRAM1_D7 SRAM1_D8 SRAM1_D9 SRAM1_D10 SRAM1_D11 SRAM1_D12 SRAM1_D13 SRAM1_D14 SRAM1_D15
net class SRAM2_A[18..0]: SRAM2_A0 SRAM2_A1 SRAM2_A2 SRAM2_A3 SRAM2_A4 SRAM2_A5 SRAM2_A6 SRAM2_A7 SRAM2_A8 SRAM2_A9 SRAM2_A10 SRAM2_A11 SRAM2_A12 SRAM2_A13 SRAM2_A14 SRAM2_A15 SRAM2_A16 SRAM2_A17 SRAM2_A18
component class U_1WB_DS2406_EPROM: C1 C2 U1
component class U_DaughterBoard_LEDS: C71 LED1 LED2 R1 R2 U2
component class U_SRAM_K6R4016V1D-TC10T_256Kx161: C99 C100 C101 C102 U9
component class U_SRAM_K6R4016V1D-TC10T_256Kx162: C1_SM C2_SM C4_SM C103 C104 C105 C106 U1_SM U10
component class U_PSU_MAX1831_1V2_ALT: C80 C81 C82 C83 C84 C85 C86 C87 L1 R23 R24 R25 R26 R27 TP7 TP8 U5
component class U_Bypass_2V5: C20_FP C23 C24 C24_FP C25 C25_FP C26 C27 C27_FP C28 C29 C30 C30_FP C31 C31_FP C32_FP C33_FP C34_FP C37_FP
net class BUS_A[24..1]: BUS_A1 BUS_A2 BUS_A3 BUS_A4 BUS_A5 BUS_A6 BUS_A7 BUS_A8 BUS_A9 BUS_A10 BUS_A11 BUS_A12 BUS_A13 BUS_A14 BUS_A15 BUS_A16 BUS_A17 BUS_A18 BUS_A19 BUS_A20 BUS_A21 BUS_A22 BUS_A23 BUS_A24
net class SRAM2_D[15..0]: SRAM2_D0 SRAM2_D1 SRAM2_D2 SRAM2_D3 SRAM2_D4 SRAM2_D5 SRAM2_D6 SRAM2_D7 SRAM2_D8 SRAM2_D9 SRAM2_D10 SRAM2_D11 SRAM2_D12 SRAM2_D13 SRAM2_D14 SRAM2_D15
component class U_PSU_MAX8860_ADJ: C88 C89 C90 R28 R29 U6
component class U_PSU: NT8 R22 TP1 TP2 TP3 TP4 TP5

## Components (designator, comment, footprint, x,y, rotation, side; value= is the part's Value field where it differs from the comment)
"Altium Logo Bot1" "Altium" Logo-Altium 55.3,3.3 r180 bottom
"Altium Logo Top1" "Altium" Logo-Altium 26.7,3.3 r0 top
C1 "0.1uF 16V" CAPC1005-STAR 71.3,76.6 r180 bottom
C2 "10nF 16V" CAPC1005-STAR 71.3,75.4 r0 bottom
C3 "220uF 10V" CAPC7343-STAR 63.3,39.4 r0 bottom (schematic designator C5_MB)
C4 "10uF 10V" CAPC2012-STAR 22.6,39.4 r90 bottom (schematic designator C1_FP)
C5 "10uF 10V" CAPC2012-STAR 54.701,35.4 r270 bottom (schematic designator C2_FP)
C6 "10uF 10V" CAPC2012-STAR 54.7,39.4 r90 bottom (schematic designator C3_FP)
C7 "0.1uF 16V" CAPC1005-STAR 43,33.4 r0 bottom (schematic designator C4_FP)
C8 "0.1uF 16V" CAPC1005-STAR 41.7,35.7 r90 bottom (schematic designator C5_FP)
C9 "0.1uF 16V" CAPC1005-STAR 38,36.2 r0 bottom (schematic designator C6_FP)
C10 "0.1uF 16V" CAPC1005-STAR 39.4,38.6 r180 bottom (schematic designator C7_FP)
C11 "0.1uF 16V" CAPC1005-STAR 37.2,34.4 r0 bottom (schematic designator C8_FP)
C12 "0.1uF 16V" CAPC1005-STAR 40.4,41.4 r180 bottom (schematic designator C9_FP)
C13 "0.1uF 16V" CAPC1005-STAR 37.5,38.1 r270 bottom (schematic designator C10_FP)
C14 "0.1uF 16V" CAPC1005-STAR 35.7,39.1 r270 bottom (schematic designator C11_FP)
C15 "10nF 16V" CAPC1005-STAR 39.9,36.7 r90 bottom (schematic designator C12_FP)
C16 "10nF 16V" CAPC1005-STAR 42.7,35.7 r90 bottom (schematic designator C13_FP)
C17 "10nF 16V" CAPC1005-STAR 42.2,39.6 r180 bottom (schematic designator C14_FP)
C18 "10nF 16V" CAPC1005-STAR 36.6,40.9 r270 bottom (schematic designator C15_FP)
C19 "10nF 16V" CAPC1005-STAR 34.7,35.7 r90 bottom (schematic designator C16_FP)
C20 "10nF 16V" CAPC1005-STAR 35.7,35.7 r90 bottom (schematic designator C17_FP)
C21 "10nF 16V" CAPC1005-STAR 40.4,40.4 r180 bottom (schematic designator C18_FP)
C22 "10nF 16V" CAPC1005-STAR 34.7,39.1 r270 bottom (schematic designator C19_FP)
C23 "220uF 10V" CAPC7343-STAR 45.3,79.8 r180 bottom (schematic designator C3_MB)
C24 "10uF 10V" CAPC2012-STAR 39.7,23.2 r180 bottom (schematic designator C21_FP)
C25 "0.1uF 16V" CAPC1005-STAR 40.4,42.4 r180 bottom (schematic designator C22_FP)
C26 "0.1uF 16V" CAPC1005-STAR 42.7,37.8 r270 bottom (schematic designator C23_FP)
C27 "0.1uF 16V" CAPC1005-STAR 40.5,32.9 r90 bottom (schematic designator C26_FP)
C28 "10nF 16V" CAPC1005-STAR 37.7,41.9 r270 bottom (schematic designator C28_FP)
C29 "10nF 16V" CAPC1005-STAR 33.7,39.8 r90 bottom (schematic designator C29_FP)
C30 "10nF 16V" CAPC1005-STAR 43.7,34.8 r270 bottom (schematic designator C35_FP)
C31 "10nF 16V" CAPC1005-STAR 36.1,32.3 r0 bottom (schematic designator C36_FP)
C32 "10uF 10V" CAPC2012-STAR 31.5,53.5 r0 bottom (schematic designator C38_FP)
C33 "10uF 10V" CAPC2012-STAR 22.6,43.6 r270 bottom (schematic designator C39_FP)
C34 "10uF 10V" CAPC2012-STAR 45.903,53.474 r180 bottom (schematic designator C40_FP)
C35 "10uF 10V" CAPC2012-STAR 22.6,30.2 r90 bottom (schematic designator C41_FP)
C36 "10uF 10V" CAPC2012-STAR 54.7,43.4 r270 bottom (schematic designator C42_FP)
C37 "10uF 10V" CAPC2012-STAR 54.8,30.1 r90 bottom (schematic designator C43_FP)
C38 "10uF 10V" CAPC2012-STAR 45,21.3 r180 bottom (schematic designator C44_FP)
C39 "10uF 10V" CAPC2012-STAR 31.4,21.3 r0 bottom (schematic designator C45_FP)
C40 "0.1uF 16V" CAPC1005-STAR 32.7,32.1 r270 bottom (schematic designator C50_FP)
C41 "0.1uF 16V" CAPC1005-STAR 44.2,42.65 r180 bottom (schematic designator C53_FP)
C42 "0.1uF 16V" CAPC1005-STAR 26.2,39.65 r180 bottom (schematic designator C54_FP)
C43 "0.1uF 16V" CAPC1005-STAR 43.4,49.4 r180 bottom (schematic designator C55_FP)
C44 "0.1uF 16V" CAPC1005-STAR 26.699,46.9 r90 bottom (schematic designator C57_FP)
C45 "10nF 16V" CAPC1005-STAR 49.2,25.399 r0 bottom (schematic designator C62_FP)
C46 "10nF 16V" CAPC1005-STAR 64.451,70.401 r90 bottom (schematic designator C63_FP)
C47 "10nF 16V" CAPC1005-STAR 34.4,49.4 r180 bottom (schematic designator C64_FP)
C48 "10nF 16V" CAPC1005-STAR 49.2,49.4 r0 bottom (schematic designator C66_FP)
C49 "10nF 16V" CAPC1005-STAR 34.7,24.899 r90 bottom (schematic designator C67_FP)
C50 "10nF 16V" CAPC1005-STAR 42.5,42.1 r270 bottom (schematic designator C68_FP)
C51 "10nF 16V" CAPC1005-STAR 40.4,49.4 r180 bottom (schematic designator C70_FP)
C52 "10nF 16V" CAPC1005-STAR 43.9,40.7 r270 bottom (schematic designator C74_FP)
C53 "10nF 16V" CAPC1005-STAR 34,41.4 r0 bottom (schematic designator C75_FP)
C54 "10nF 16V" CAPC1005-STAR 31.95,50.4 r90 bottom (schematic designator C76_FP)
C55 "10nF 16V" CAPC1005-STAR 26.199,38.15 r0 bottom (schematic designator C77_FP)
C56 "10nF 16V" CAPC1005-STAR 34.5,32 r90 bottom (schematic designator C78_FP)
C57 "10nF 16V" CAPC1005-STAR 26.699,30.9 r90 bottom (schematic designator C80_FP)
C58 "10nF 16V" CAPC1005-STAR 41.9,31.9 r90 bottom (schematic designator C83_FP)
C59 "10nF 16V" CAPC1005-STAR 33.7,33 r270 bottom (schematic designator C84_FP)
C60 "10nF 16V" CAPC1005-STAR 52.701,37.4 r0 bottom (schematic designator C85_FP)
C61 "10nF 16V" CAPC1005-STAR 38.2,43.3 r180 bottom (schematic designator C86_FP)
C62 "10nF 16V" CAPC1005-STAR 50.701,30.9 r90 bottom (schematic designator C87_FP)
C63 "10nF 16V" CAPC1005-STAR 35.5,42.9 r270 bottom (schematic designator C89_FP)
C64 "10nF 16V" CAPC1005-STAR 50.7,33.1 r270 bottom (schematic designator C92_FP)
C65 "10nF 16V" CAPC1005-STAR 44.2,32.6 r180 bottom (schematic designator C94_FP)
C66 "10nF 16V" CAPC1005-STAR 33.7,35.7 r90 bottom (schematic designator C96_FP)
C67 "10nF 16V" CAPC1005-STAR 38.2,32.6 r0 bottom (schematic designator C99_FP)
C68 "10nF 16V" CAPC1005-STAR 28.199,49.4 r180 bottom (schematic designator C100_FP)
C69 "220uF 10V" CAPC7343-STAR 20.4,84.1 r180 bottom (schematic designator C1_MB)
C70 "220uF 10V" CAPC7343-STAR 47.5,72.7 r180 bottom (schematic designator C2_MB)
C71 "0.1uF 16V" CAPC1005-STAR 32,6 r0 bottom (schematic designator C1_SL)
C72 "0.1uF 16V" CAPC1005-STAR 60.2,71.1 r180 bottom (schematic designator C1)
C73 "0.1uF 16V" CAPC1005-STAR 57.5,82.125 r180 bottom (schematic designator C2)
C74 "10nF 16V" CAPC1005-STAR 55.4,75.4 r270 bottom (schematic designator C3)
C75 "10nF 16V" CAPC1005-STAR 60.2,72.1 r180 bottom (schematic designator C4)
C76 "10nF 16V" CAPC1005-STAR 57.5,80.925 r180 bottom (schematic designator C5)
C77 "0.1uF 16V" CAPC1005-STAR 54.4,75.4 r270 bottom (schematic designator C6)
C78 "10uF 10V" CAPC2012-STAR 70.25,78.425 r0 bottom (schematic designator C23_CM)
C79 "10uF 10V" CAPC2012-STAR 56.3,101.25 r270 bottom (schematic designator C24_CM)
C80 "470pF 50V" CAPC1005-STAR 74.8,44.2 r90 top (schematic designator C2_PS)
C81 "2.2uF 10V" CAPC1608-STAR 62.4,43 r180 top (schematic designator C4_PS)
C82 "220uF 10V" CAPC7343-STAR 71.5,54.6 r180 top (schematic designator C3_PS)
C83 "10uF 10V" CAPC2012-STAR 75.9,36.2 r270 top (schematic designator C5_PS)
C84 "22uF 10V" CAPC3225-STAR 69.8,38.2 r180 top (schematic designator C6_PS)
C85 "10uF 10V" CAPC2012-STAR 79.2,45.6 r270 top (schematic designator C8_PS)
C86 "22uF 10V" CAPC3225-STAR 67,50.2 r180 top (schematic designator C1_PS)
C87 "1uF 25V" CAPC3216-STAR 62.2,45.3 r0 top (schematic designator C7_PS)
C88 "2.2uF 10V" CAPC1608-STAR 39.3,73 r180 bottom (schematic designator C3_LD)
C89 "2.2uF 10V" CAPC1608-STAR 33.7,75.3 r270 bottom (schematic designator C1_LD)
C90 "0.033uF 10V" CAPC1005-STAR 34.3,72.8 r270 bottom (schematic designator C2_LD)
C91 "0.1uF 16V" CAPC1005-STAR 54.6,101.8 r270 top (schematic designator C1)
C92 "0.1uF 16V" CAPC1005-STAR 39,85.7 r180 top (schematic designator C2)
C93 "0.1uF 16V" CAPC1005-STAR 32.5,86.5 r180 bottom (schematic designator C3)
C94 "0.1uF 16V" CAPC1005-STAR 45.8,101.6 r90 bottom (schematic designator C4)
C95 "10nF 16V" CAPC1005-STAR 36.6,101.1 r180 top (schematic designator C5)
C96 "10nF 16V" CAPC1005-STAR 41.4,101.1 r180 top (schematic designator C6)
C97 "10nF 16V" CAPC1005-STAR 51.8,85.7 r180 bottom (schematic designator C7)
C98 "10nF 16V" CAPC1005-STAR 47,85.7 r180 bottom (schematic designator C8)
C99 "0.1uF 16V" CAPC1005-STAR 74.052,26.9 r90 top (schematic designator C1_SM)
C100 "0.1uF 16V" CAPC1005-STAR 58.652,26.8 r270 top (schematic designator C2_SM)
C101 "10nF 16V" CAPC1005-STAR 74.052,24.9 r270 top (schematic designator C3_SM)
C102 "10nF 16V" CAPC1005-STAR 57.4,26.8 r270 top (schematic designator C4_SM)
C103 "0.1uF 16V" CAPC1005-STAR 60.752,24.9 r270 bottom (schematic designator C1_SM)
C104 "0.1uF 16V" CAPC1005-STAR 76.4,28.8 r90 bottom (schematic designator C2_SM)
C105 "10nF 16V" CAPC1005-STAR 60.752,27 r90 bottom (schematic designator C3_SM)
C106 "10nF 16V" CAPC1005-STAR 76.4,26.8 r270 bottom (schematic designator C4_SM)
C107 "0.1uF 16V" CAPC1005-STAR 66.143,84.5 r0 top (schematic designator C1)
C108 "0.1uF 16V" CAPC1005-STAR 66.1,102.3 r180 top (schematic designator C2)
C109 "0.1uF 16V" CAPC1005-STAR 66.1,84.6 r0 bottom (schematic designator C3)
C110 "0.1uF 16V" CAPC1005-STAR 67.7,102.3 r0 bottom (schematic designator C4)
C111 "10nF 16V" CAPC1005-STAR 66.143,85.6 r0 top (schematic designator C5)
C112 "10nF 16V" CAPC1005-STAR 66.093,101.2 r180 top (schematic designator C6)
C113 "10nF 16V" CAPC1005-STAR 66.1,85.6 r0 bottom (schematic designator C7)
C114 "10nF 16V" CAPC1005-STAR 67.7,101.2 r0 bottom (schematic designator C8)
FD1 "Fiducial - Round" "FIDUCIAL ROUND" 78.004,93.005 r0 top
FD2 "Fiducial - Round" "FIDUCIAL ROUND" 15.001,13.501 r0 top
HDR_B1 "MOLEX - 54075-1009" 54075 48.1,12 r0 bottom locked (schematic designator HDR_B)
HDR_L1 "MOLEX - 54075-1009" 54075 7.8,37.4 r270 bottom locked (schematic designator HDR_L)
HDR_T1 "MOLEX - 54075-1009" 54075 48.1,62.8 r0 bottom locked (schematic designator HDR_T)
L1 "2u2, 15A, 4R2, SMD" IND-EPCOS-SMD-B82559 74.8,41.9 r90 bottom (schematic designator L1_PS)
LED1 "GREEN" LED2012-STAR 32.05,4.3 r180 top (schematic designator LED2_SL)
LED2 "RED" LED2012-STAR 50.15,4.3 r180 top (schematic designator LED1_SL)
MH1 "MOUNTING HOLE 3MM" MOUNTING_HOLE_3MM 41.1,3.3 r180 top
MH2 "MOUNTING HOLE 3MM" MOUNTING_HOLE_3MM 3.3,109.9 r180 top
MH3 "MOUNTING HOLE 3MM" MOUNTING_HOLE_3MM 78.9,109.9 r180 top
NT1 "Net Tie SMT2" NETTIE-SMT2-8X8 41.306,68.591 r90 bottom net-tie
NT2 "Net Tie SMT2" NETTIE-SMT2-8X8 37.191,6.569 r0 bottom net-tie (schematic designator NT6)
NT3 "Net Tie SMT2" NETTIE-SMT2-8X8 44.506,68.091 r90 bottom net-tie (schematic designator NT2)
NT4 "Net Tie SMT2" NETTIE-SMT2-8X8 39.394,54.991 r90 top net-tie (schematic designator NT8)
NT5 "Net Tie SMT2" NETTIE-SMT2-8X8 43.706,68.091 r90 bottom net-tie (schematic designator NT3)
NT6 "Net Tie SMT2" NETTIE-SMT2-8X8 42.906,68.091 r90 bottom net-tie (schematic designator NT4)
NT7 "Net Tie SMT2" NETTIE-SMT2-8X8 42.106,68.091 r90 bottom net-tie (schematic designator NT5)
NT8 "Net Tie SMT2" NETTIE-SMT2-8X8 63.994,50.364 r90 top net-tie (schematic designator NT7)
PBFREE "" LEAD_FREE_S 78,73.4 r180 bottom
PBFREE1 "" LEAD_FREE_S 14.7,101.7 r180 bottom
PCB1 "DB46 Blank PCB" "DB46 Blank PCB" 82.1,2.32 r90 top
R1 "270R 1%" RESC1005-STAR 31.7,4.3 r180 bottom (schematic designator R2_SL)
R2 "270R 1%" RESC1005-STAR 50.15,4.3 r180 bottom (schematic designator R1_SL)
R3 "4K7 1%" RESC1005-STAR 22,54.5 r180 bottom (schematic designator R1)
R4 "100R 1%" RESC1005-STAR 25,54.5 r0 bottom (schematic designator R7)
R5 "4K7 1%" RESC1005-STAR 54.1,53.5 r90 bottom (schematic designator R2)
R6 "100R 1%" RESC1005-STAR 50,53.5 r270 bottom (schematic designator R8)
R7 "100R 1%" RESC1005-STAR 52,53.5 r270 bottom (schematic designator R9)
R8 "4K7 1%" RESC1005-STAR 47.2,76.2 r180 bottom (schematic designator R3)
R9 "100R 1%" RESC1005-STAR 54.1,51.4 r270 bottom (schematic designator R10)
R10 "100R 1%" RESC1005-STAR 25,53.2 r180 bottom (schematic designator R12)
R11 "4K7 1%" RESC1005-STAR 55,23.6 r180 bottom (schematic designator R4)
R12 "100R 1%" RESC1005-STAR 22.5,23.5 r0 bottom (schematic designator R14)
R13 "100R 1%" RESC1005-STAR 22.5,24.6 r0 bottom (schematic designator R18)
R14 "100R 1%" RESC1005-STAR 22.5,22.4 r0 bottom (schematic designator R23)
R15 "100R 1%" RESC1005-STAR 22,53.2 r180 bottom (schematic designator R24)
R16 "100R 1%" RESC1005-STAR 52.451,42.4 r270 bottom (schematic designator R22)
R17 "100R 1%" RESC1005-STAR 52.451,40.15 r270 bottom (schematic designator R20)
R22 "100K 1%" RESC1005-STAR 36.9,72.8 r270 bottom (schematic designator R1T)
R23 "10R 1%" RESC1005-STAR 63.3,41.2 r90 top (schematic designator R2_PS)
R24 "2K7 1%" RESC1005-STAR 70.8,47.4 r0 top (schematic designator R1_PS)
R25 "27K 1%" RESC1005-STAR 73.4,47.4 r0 top (schematic designator R3_PS)
R26 "2K7 1%" RESC1005-STAR 76,47.4 r0 top (schematic designator R4_PS)
R27 "100K 1%" RESC1005-STAR 76,46.1 r0 top (schematic designator R5_PS)
R28 "100K 1%" RESC1005-STAR 37.9,77.6 r180 bottom (schematic designator R1_LD)
R29 "100K 1%" RESC1005-STAR 35.6,72.8 r270 bottom (schematic designator R2_LD)
RN1 "RESNET 4 x 100R" RESNET-1005X4 42.24,83.85 r90 bottom (schematic designator RN33)
RN2 "RESNET 4 x 100R" RESNET-1005X4 34.715,83.85 r90 bottom (schematic designator RN35)
RN3 "RESNET 4 x 100R" RESNET-1005X4 39.615,102.25 r90 bottom (schematic designator RN37)
RN4 "RESNET 4 x 100R" RESNET-1005X4 45.9,83.9 r270 bottom (schematic designator RN34)
RN5 "RESNET 4 x 100R" RESNET-1005X4 43.215,102.25 r270 bottom (schematic designator RN38)
RN6 "RESNET 4 x 100R" RESNET-1005X4 38.315,83.85 r270 bottom (schematic designator RN36)
TP1 "GND" TestPin 73.043,79.722 r0 top (schematic designator TP0)
TP2 "3V3" TestPin 73.043,77.182 r0 top (schematic designator TP1)
TP3 "2V5" TestPin 73.043,74.642 r0 top (schematic designator TP2)
TP4 "5V0" TestPin 73.043,72.102 r0 top (schematic designator TP3)
TP5 "1V2" TestPin 73.043,69.562 r0 top (schematic designator TP4)
U1 "DS2406" TSOC6 68.9,72.3 r90 bottom
U2 "SN74LVC1G04DBV" SOT95P280-5 35.5,4.2 r0 bottom (schematic designator U1_SL)
U3 "S29GL256N11FFIV10" BGA100P8X8-64 60.2,77.125 r180 top locked (schematic designator U1)
U4 "XC4VSX35-10FFG668C" XC4VLX25-10FF668C 38.7,37.4 r0 top locked (schematic designator U1)
U5 "MAX1831EEE" SOP63P602-16 68.798,43.707 r180 top locked (schematic designator U1_PS)
U6 "MAX8860EUA18+" SOP65P490-8 37.9,75.4 r180 bottom (schematic designator U11)
U7 "SDRAM-16Mx16" TSOP80P1176-54 44.2,93.4 r0 top (schematic designator U1)
U8 "SDRAM-16Mx16" TSOP80P1176-54 44.2,93.4 r180 bottom (schematic designator U2)
U9 "SRAM-256Kx16" TSOP80P1176-44 66.352,26.9 r90 top (schematic designator U1_SM)
U10 "SRAM-256Kx16" TSOP80P1176-44 68.652,26.9 r90 bottom (schematic designator U1_SM)
U11 "SRAM-256Kx16" TSOP80P1176-44 66.1,93.4 r0 top (schematic designator U1)
U12 "SRAM-256Kx16" TSOP80P1176-44 67.7,93.4 r180 bottom (schematic designator U2)

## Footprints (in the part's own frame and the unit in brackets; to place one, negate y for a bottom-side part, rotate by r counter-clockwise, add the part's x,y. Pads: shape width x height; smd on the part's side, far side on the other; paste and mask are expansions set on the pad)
54075 [mm]
  rect 0.5x1.9 smd: 1(-19.6,3.4) 2(-19.6,-3.4) 3(-18.8,3.4) 4(-18.8,-3.4) 5(-18,3.4) 6(-18,-3.4) 7(-17.2,3.4) 8(-17.2,-3.4) 9(-16.4,3.4) 10(-16.4,-3.4) 11(-15.6,3.4) 12(-15.6,-3.4) 13(-14.8,3.4) 14(-14.8,-3.4) 15(-14,3.4) 16(-14,-3.4) 17(-13.2,3.4) 18(-13.2,-3.4) 19(-12.4,3.4) 20(-12.4,-3.4) 21(-11.6,3.4) 22(-11.6,-3.4) 23(-10.8,3.4) 24(-10.8,-3.4) 25(-10,3.4) 26(-10,-3.4) 27(-9.2,3.4) 28(-9.2,-3.4) 29(-8.4,3.4) 30(-8.4,-3.4) 31(-7.6,3.4) 32(-7.6,-3.4) 33(-6.8,3.4) 34(-6.8,-3.4) 35(-6,3.4) 36(-6,-3.4) 37(-5.2,3.4) 38(-5.2,-3.4) 39(-4.4,3.4) 40(-4.4,-3.4) 41(-3.6,3.4) 42(-3.6,-3.4) 43(-2.8,3.4) 44(-2.8,-3.4) 45(-2,3.4) 46(-2,-3.4) 47(-1.2,3.4) 48(-1.2,-3.4) 49(-0.4,3.4) 50(-0.4,-3.4) 51(0.4,3.4) 52(0.4,-3.4) 53(1.2,3.4) 54(1.2,-3.4) 55(2,3.4) 56(2,-3.4) 57(2.8,3.4) 58(2.8,-3.4) 59(3.6,3.4) 60(3.6,-3.4) 61(4.4,3.4) 62(4.4,-3.4) 63(5.2,3.4) 64(5.2,-3.4) 65(6,3.4) 66(6,-3.4) 67(6.8,3.4) 68(6.8,-3.4) 69(7.6,3.4) 70(7.6,-3.4) 71(8.4,3.4) 72(8.4,-3.4) 73(9.2,3.4) 74(9.2,-3.4) 75(10,3.4) 76(10,-3.4) 77(10.8,3.4) 78(10.8,-3.4) 79(11.6,3.4) 80(11.6,-3.4) 81(12.4,3.4) 82(12.4,-3.4) 83(13.2,3.4) 84(13.2,-3.4) 85(14,3.4) 86(14,-3.4) 87(14.8,3.4) 88(14.8,-3.4) 89(15.6,3.4) 90(15.6,-3.4) 91(16.4,3.4) 92(16.4,-3.4) 93(17.2,3.4) 94(17.2,-3.4) 95(18,3.4) 96(18,-3.4) 97(18.8,3.4) 98(18.8,-3.4) 99(19.6,3.4) 100(19.6,-3.4)
  round 1.6 hole 0.7: MH1(-26.7,4.2) MH2(-25.9,-4.2) MH3(26.7,4.2) MH4(25.9,-4.2)
  round 4.8 hole 5.1 unplated: MH5(-26.3,0) MH6(26.3,0)
  Top Layer keep-out region: -20.15,2.15 20.15,2.15 20.15,-2.15 -20.15,-2.15
  silkscreen extent -30.35,-4.4 30.35,5.02, body extent -30.36,-4.42 30.34,4.38, height 3.75
BGA100P8X8-64 [mm] "AMD 64-Ball Fortfied Ball grid Array (FBGA)"
  round 0.5 smd: A1(-3.5,-3.5) A2(-3.5,-2.5) A3(-3.5,-1.5) A4(-3.5,-0.5) A5(-3.5,0.5) A6(-3.5,1.5) A7(-3.5,2.5) A8(-3.5,3.5) B1(-2.5,-3.5) B2(-2.5,-2.5) B3(-2.5,-1.5) B4(-2.5,-0.5) B5(-2.5,0.5) B6(-2.5,1.5) B7(-2.5,2.5) B8(-2.5,3.5) C1(-1.5,-3.5) C2(-1.5,-2.5) C3(-1.5,-1.5) C4(-1.5,-0.5) C5(-1.5,0.5) C6(-1.5,1.5) C7(-1.5,2.5) C8(-1.5,3.5) D1(-0.5,-3.5) D2(-0.5,-2.5) D3(-0.5,-1.5) D4(-0.5,-0.5) D5(-0.5,0.5) D6(-0.5,1.5) D7(-0.5,2.5) D8(-0.5,3.5) E1(0.5,-3.5) E2(0.5,-2.5) E3(0.5,-1.5) E4(0.5,-0.5) E5(0.5,0.5) E6(0.5,1.5) E7(0.5,2.5) E8(0.5,3.5) F1(1.5,-3.5) F2(1.5,-2.5) F3(1.5,-1.5) F4(1.5,-0.5) F5(1.5,0.5) F6(1.5,1.5) F7(1.5,2.5) F8(1.5,3.5) G1(2.5,-3.5) G2(2.5,-2.5) G3(2.5,-1.5) G4(2.5,-0.5) G5(2.5,0.5) G6(2.5,1.5) G7(2.5,2.5) G8(2.5,3.5) H1(3.5,-3.5) H2(3.5,-2.5) H3(3.5,-1.5) H4(3.5,-0.5) H5(3.5,0.5) H6(3.5,1.5) H7(3.5,2.5) H8(3.5,3.5)
  silkscreen extent -6.5,-6.32 6.5,5.5, body extent -6.35,-5.4 6.41,5.36, height 1
CAPC1005-STAR [mm] "Chip Capacitor 1005"
  rect 0.6x0.6 smd: 1(-0.525,0) 2(0.525,0)
  silkscreen extent -0.05,-0.38 0.05,0.38, body extent -0.57,-0.3 0.57,0.3, height 0.2
CAPC1608-STAR [mm] "Capacitor SMD 0603 (1608)"
  rect 0.9x0.8 smd: 1(-0.8,0) 2(0.8,0)
  silkscreen extent 0,-0.4 0,0.4, body extent -1.11,-0.41 1.1,0.39, height 0.8
CAPC2012-STAR [mm] "0805 Capacitor SMD - Startronics"
  rect 1x1.25 smd: 1(-1,0) 2(1,0)
  silkscreen extent -0.4,-1 0.4,1, body extent -1.32,-0.69 1.23,0.67, height 0.5
CAPC3216-STAR [mm] "Capacitor 1206 (3216) for Startronics"
  rect 1x1.6 smd: 1(-1.45,0) 2(1.45,0)
  silkscreen extent -0.62,-1.1 0.62,1.1, body extent -1.64,-0.89 1.63,0.86, height 0.9
CAPC3225-STAR [mm] "1210 Capacitor SMD - Startronics"
  rect 1x2.75 smd: 1(-1.5,0) 2(1.5,0)
  silkscreen extent -0.7,-1.5 0.7,1.5, body extent -1.94,-1.2 1.89,1.29, height 1.5
CAPC7343-STAR [mm] "Capcacitor SMD 7.3 x 4.3mm (D-Case)"
  rect 2.6x2.4 smd: 1(-3.202,0.007) 2(3.198,0.007)
  silkscreen extent -5.32,-2.39 5.08,2.41, body extent -3.49,-2.03 3.51,2.04, height 4.05
"DB46 Blank PCB" [mm]
"FIDUCIAL ROUND" [mm] "FIDUCIAL ROUND"
  round 1.5 all layers, no hole paste+0 mask+1.1: 0(0,0)
  Top Layer circle w0.127: c0,0 r1.778
  Bottom Layer circle w0.127: c0,0 r1.778
  Keep-Out Layer circle w0.1: c0,0 r1.9
IND-EPCOS-SMD-B82559 [mm]
  rect 4.4x10.4 smd: 1(0,0) 2(8.4,0)
  silkscreen extent -2.5,-5.5 11,5.5, body extent -2.55,-5.3 10.9,5.6, height 4.95
LEAD_FREE_S [mm]
  silkscreen extent -3.17,-3.17 3.17,3.17
LED2012-STAR [mm] "0805 LED SMD - Startronics"
  rect 1x1.25 smd: 1(1,0) 2(-1,0)
  silkscreen extent -2.27,-1 1.8,1, body extent -1.6,-0.6 1.5,0.6, height 0.67
Logo-Altium [mm]
  silkscreen extent -26.04,-2.51 -14.12,2.59
MOUNTING_HOLE_3MM [mm] "Non-plated mounting hole for 3mm screw"
  round 3.8 hole 3.4 mask+0.2: MOUNT(0,0)
  Top Layer circle w1: c0,0 r2.3
  Top Layer region: -2.8,-2.8 2.8,-2.8 2.8,2.8 -2.8,2.8
  Top Layer keep-out region: -3.3,-3.3 3.3,-3.3 3.3,3.3 -3.3,3.3
  Bottom Layer region: -2.8,-2.8 2.8,-2.8 2.8,2.8 -2.8,2.8
  Bottom Layer keep-out region: -3.3,-3.3 3.3,-3.3 3.3,3.3 -3.3,3.3
  Keep-Out Layer circle w1.2: c0,0 r2.5
NETTIE-SMT2-8X8 [mm]
  rect 0.4x0.2 smd paste-0.11 mask-0.11: 1(-0.891,-0.006) 2(-0.691,-0.006)
RESC1005-STAR [mm] "Chip Inductor 1005"
  rect 0.575x0.6 smd: 1(-0.538,0) 2(0.538,0)
  silkscreen extent -0.05,-0.38 0.05,0.38, body extent -0.71,-0.25 0.72,0.26, height 0.25
RESNET-1005X4 [mm] "Resistor network 4 x 1005 (0402)"
  rect 0.3x0.83 smd: 1(-0.75,-0.64) 2(-0.25,-0.64) 3(0.25,-0.64) 4(0.75,-0.64) 5(0.75,0.64) 6(0.25,0.64) 7(-0.25,0.64) 8(-0.75,0.64)
  silkscreen extent -1.15,-1 1.15,1, body extent -0.92,-0.84 1.04,0.81, height 0.4
SOP63P602-16 [mil]
  rect 82x16 smd: 1(-116,87.5) 2(-116,62) 3(-116,37.5) 4(-116,12.5) 5(-116,-12.5) 6(-116,-37.5) 7(-116,-62.5) 8(-116,-87.5) 9(116,-87.5) 10(116,-62.5) 11(116,-37.5) 12(116,-12.5) 13(116,12.5) 14(116,37.5) 15(116,62.5) 16(116,87.5)
  silkscreen extent -100,-100 60,125, body extent -107,-100 108,103, height 29
SOP65P490-8 [mm]
  rect 1.5x0.35 smd: 1(-2.275,0.975) 2(-2.3,0.325) 3(-2.3,-0.325) 4(-2.3,-0.975) 5(2.275,-0.975) 6(2.275,-0.325) 7(2.3,0.325) 8(2.3,0.975)
  silkscreen extent -2.38,-1.3 1.3,1.75, body extent -2.39,-1.23 2.41,1.28, height 1
SOT95P280-5 [mm] "SOT-23/SC-74A; 5 Leads; Body 3.1 x 3 mm, inc. leads (LxW max)"
  rect 0.6x1.3 smd: 1(-0.95,-1.4) 2(0,-1.4) 3(0.95,-1.4) 4(0.95,1.4)
  rect 0.6x1.25 smd: 5(-0.95,1.4)
  silkscreen extent -1.55,-0.9 1.55,0.9, body extent -1.51,-1.49 1.52,1.52, height 0.8
TestPin [mil]
  round 60 hole 35.43: 1(0,0)
  silkscreen extent -41,-39 156,39
TSOC6 [mil]
  rect 25x71 smd: 1(-50,-75) 2(0,-75) 3(50,-75) 4(50,75) 5(0,75) 6(-50,75)
  silkscreen extent -115,-80 85,80, body extent -79,-90 84,91, height 40
TSOP80P1176-44 [mm]
  rect 0.5x1.4 smd: 1(-8.4,-5.7) 2(-7.6,-5.7) 3(-6.8,-5.7) 4(-6,-5.7) 5(-5.2,-5.7) 6(-4.4,-5.7) 7(-3.6,-5.7) 8(-2.8,-5.7) 9(-2,-5.7) 10(-1.2,-5.7) 11(-0.4,-5.7) 12(0.4,-5.7) 13(1.2,-5.7) 14(2,-5.7) 15(2.8,-5.7) 16(3.6,-5.7) 17(4.4,-5.7) 18(5.2,-5.7) 19(6,-5.7) 20(6.8,-5.7) 21(7.6,-5.7) 22(8.4,-5.7) 23(8.4,5.7) 24(7.6,5.7) 25(6.8,5.7) 26(6,5.7) 27(5.2,5.7) 28(4.4,5.7) 29(3.6,5.7) 30(2.8,5.7) 31(2,5.7) 32(1.2,5.7) 33(0.4,5.7) 34(-0.4,5.7) 35(-1.2,5.7) 36(-2,5.7) 37(-2.8,5.7) 38(-3.6,5.7) 39(-4.4,5.7) 40(-5.2,5.7) 41(-6,5.7) 42(-6.8,5.7) 43(-7.6,5.7) 44(-8.4,5.7)
  silkscreen extent -9.29,-5.7 9.26,4.45, body extent -9.24,-5.95 9.26,5.84, height 1
TSOP80P1176-54 [mm] "Plastic Small Outline; 54 Leads; Body Width 10.16 mm"
  rect 0.5x1.4 smd: 1(-10.4,-5.7) 2(-9.6,-5.7) 3(-8.8,-5.7) 4(-8,-5.7) 5(-7.2,-5.7) 6(-6.4,-5.7) 7(-5.6,-5.7) 8(-4.8,-5.7) 9(-4,-5.7) 10(-3.2,-5.7) 11(-2.4,-5.7) 12(-1.6,-5.7) 13(-0.8,-5.7) 14(0,-5.7) 15(0.8,-5.7) 16(1.6,-5.7) 17(2.4,-5.7) 18(3.2,-5.7) 19(4,-5.7) 20(4.8,-5.7) 21(5.6,-5.7) 22(6.4,-5.7) 23(7.2,-5.7) 24(8,-5.7) 25(8.8,-5.7) 26(9.6,-5.7) 27(10.4,-5.7) 28(10.4,5.7) 29(9.6,5.7) 30(8.8,5.7) 31(8,5.7) 32(7.2,5.7) 33(6.4,5.7) 34(5.6,5.7) 35(4.8,5.7) 36(4,5.7) 37(3.2,5.7) 38(2.4,5.7) 39(1.6,5.7) 40(0.8,5.7) 41(0,5.7) 42(-0.8,5.7) 43(-1.6,5.7) 44(-2.4,5.7) 45(-3.2,5.7) 46(-4,5.7) 47(-4.8,5.7) 48(-5.6,5.7) 49(-6.4,5.7) 50(-7.2,5.7) 51(-8,5.7) 52(-8.8,5.7) 53(-9.6,5.7) 54(-10.4,5.7)
  silkscreen extent -11.33,-5.67 11.15,4.4, body extent -11.23,-5.96 11.19,5.97, height 1
XC4VLX25-10FF668C [mm] "BGA, 668-Leads, Body 27x27mm, Pitch 1mm"
  round 0.5 smd: A2(-11.5,12.5) A3(-10.5,12.5) A4(-9.5,12.5) A5(-8.5,12.5) A6(-7.5,12.5) A7(-6.5,12.5) A8(-5.5,12.5) A9(-4.5,12.5) A10(-3.5,12.5) A11(-2.5,12.5) A12(-1.5,12.5) A13(-0.5,12.5) A14(0.5,12.5) A15(1.5,12.5) A16(2.5,12.5) A17(3.5,12.5) A18(4.5,12.5) A19(5.5,12.5) A20(6.5,12.5) A21(7.5,12.5) A22(8.5,12.5) A23(9.5,12.5) A24(10.5,12.5) A25(11.5,12.5) AA1(-12.5,-7.5) AA2(-11.5,-7.5) AA3(-10.5,-7.5) AA4(-9.5,-7.5) AA5(-8.5,-7.5) AA6(-7.5,-7.5) AA7(-6.5,-7.5) AA8(-5.5,-7.5) AA9(-4.5,-7.5) AA10(-3.5,-7.5) AA11(-2.5,-7.5) AA12(-1.5,-7.5) AA13(-0.5,-7.5) AA14(0.5,-7.5) AA15(1.5,-7.5) AA16(2.5,-7.5) AA17(3.5,-7.5) AA18(4.5,-7.5) AA19(5.5,-7.5) AA20(6.5,-7.5) AA21(7.5,-7.5) AA22(8.5,-7.5) AA23(9.5,-7.5) AA24(10.5,-7.5) AA25(11.5,-7.5) AA26(12.5,-7.5) AB1(-12.5,-8.5) AB2(-11.5,-8.5) AB3(-10.5,-8.5) AB4(-9.5,-8.5) AB5(-8.5,-8.5) AB6(-7.5,-8.5) AB7(-6.5,-8.5) AB8(-5.5,-8.5) AB9(-4.5,-8.5) AB10(-3.5,-8.5) AB11(-2.5,-8.5) AB12(-1.5,-8.5) AB13(-0.5,-8.5) AB14(0.5,-8.5) AB15(1.5,-8.5) AB16(2.5,-8.5) AB17(3.5,-8.5) AB18(4.5,-8.5) AB19(5.5,-8.5) AB20(6.5,-8.5) AB21(7.5,-8.5) AB22(8.5,-8.5) AB23(9.5,-8.5) AB24(10.5,-8.5) AB25(11.5,-8.5) AB26(12.5,-8.5) AC1(-12.5,-9.5) AC2(-11.5,-9.5) AC3(-10.5,-9.5) AC4(-9.5,-9.5) AC5(-8.5,-9.5) AC6(-7.5,-9.5) AC7(-6.5,-9.5) AC8(-5.5,-9.5) AC9(-4.5,-9.5) AC10(-3.5,-9.5) AC11(-2.5,-9.5) AC12(-1.5,-9.5) AC13(-0.5,-9.5) AC14(0.5,-9.5) AC15(1.5,-9.5) AC16(2.5,-9.5) AC17(3.5,-9.5) AC18(4.5,-9.5) AC19(5.5,-9.5) AC20(6.5,-9.5) AC21(7.5,-9.5) AC22(8.5,-9.5) AC23(9.5,-9.5) AC24(10.5,-9.5) AC25(11.5,-9.5) AC26(12.5,-9.5) AD1(-12.5,-10.5) AD2(-11.5,-10.5) AD3(-10.5,-10.5) AD4(-9.5,-10.5) AD5(-8.5,-10.5) AD6(-7.5,-10.5) AD7(-6.5,-10.5) AD8(-5.5,-10.5) AD9(-4.5,-10.5) AD10(-3.5,-10.5) AD11(-2.5,-10.5) AD12(-1.5,-10.5) AD13(-0.5,-10.5) AD14(0.5,-10.5) AD15(1.5,-10.5) AD16(2.5,-10.5) AD17(3.5,-10.5) AD18(4.5,-10.5) AD19(5.5,-10.5) AD20(6.5,-10.5) AD21(7.5,-10.5) AD22(8.5,-10.5) AD23(9.5,-10.5) AD24(10.5,-10.5) AD25(11.5,-10.5) AD26(12.5,-10.5) AE1(-12.5,-11.5) AE2(-11.5,-11.5) AE3(-10.5,-11.5) AE4(-9.5,-11.5) AE5(-8.5,-11.5) AE6(-7.5,-11.5) AE7(-6.5,-11.5) AE8(-5.5,-11.5) AE9(-4.5,-11.5) AE10(-3.5,-11.5) AE11(-2.5,-11.5) AE12(-1.5,-11.5) AE13(-0.5,-11.5) AE14(0.5,-11.5) AE15(1.5,-11.5) AE16(2.5,-11.5) AE17(3.5,-11.5) AE18(4.5,-11.5) AE19(5.5,-11.5) AE20(6.5,-11.5) AE21(7.5,-11.5) AE22(8.5,-11.5) AE23(9.5,-11.5) AE24(10.5,-11.5) AE25(11.5,-11.5) AE26(12.5,-11.5) AF2(-11.5,-12.5) AF3(-10.5,-12.5) AF4(-9.5,-12.5) AF5(-8.5,-12.5) AF6(-7.5,-12.5) AF7(-6.5,-12.5) AF8(-5.5,-12.5) AF9(-4.5,-12.5) AF10(-3.5,-12.5) AF11(-2.5,-12.5) AF12(-1.5,-12.5) AF13(-0.5,-12.5) AF14(0.5,-12.5) AF15(1.5,-12.5) AF16(2.5,-12.5) AF17(3.5,-12.5) AF18(4.5,-12.5) AF19(5.5,-12.5) AF20(6.5,-12.5) AF21(7.5,-12.5) AF22(8.5,-12.5) AF23(9.5,-12.5) AF24(10.5,-12.5) AF25(11.5,-12.5) B1(-12.5,11.5) B2(-11.5,11.5) B3(-10.5,11.5) B4(-9.5,11.5) B5(-8.5,11.5) B6(-7.5,11.5) B7(-6.5,11.5) B8(-5.5,11.5) B9(-4.5,11.5) B10(-3.5,11.5) B11(-2.5,11.5) B12(-1.5,11.5) B13(-0.5,11.5) B14(0.5,11.5) B15(1.5,11.5) B16(2.5,11.5) B17(3.5,11.5) B18(4.5,11.5) B19(5.5,11.5) B20(6.5,11.5) B21(7.5,11.5) B22(8.5,11.5) B23(9.5,11.5) B24(10.5,11.5) B25(11.5,11.5) B26(12.5,11.5) C1(-12.5,10.5) C2(-11.5,10.5) C3(-10.5,10.5) C4(-9.5,10.5) C5(-8.5,10.5) C6(-7.5,10.5) C7(-6.5,10.5) C8(-5.5,10.5) C9(-4.5,10.5) C10(-3.5,10.5) C11(-2.5,10.5) C12(-1.5,10.5) C13(-0.5,10.5) C14(0.5,10.5) C15(1.5,10.5) C16(2.5,10.5) C17(3.5,10.5) C18(4.5,10.5) C19(5.5,10.5) C20(6.5,10.5) C21(7.5,10.5) C22(8.5,10.5) C23(9.5,10.5) C24(10.5,10.5) C25(11.5,10.5) C26(12.5,10.5) D1(-12.5,9.5) D2(-11.5,9.5) D3(-10.5,9.5) D4(-9.5,9.5) D5(-8.5,9.5) D6(-7.5,9.5) D7(-6.5,9.5) D8(-5.5,9.5) D9(-4.5,9.5) D10(-3.5,9.5) D11(-2.5,9.5) D12(-1.5,9.5) D13(-0.5,9.5) D14(0.5,9.5) D15(1.5,9.5) D16(2.5,9.5) D17(3.5,9.5) D18(4.5,9.5) D19(5.5,9.5) D20(6.5,9.5) D21(7.5,9.5) D22(8.5,9.5) D23(9.5,9.5) D24(10.5,9.5) D25(11.5,9.5) D26(12.5,9.5) E1(-12.5,8.5) E2(-11.5,8.5) E3(-10.5,8.5) E4(-9.5,8.5) E5(-8.5,8.5) E6(-7.5,8.5) E7(-6.5,8.5) E8(-5.5,8.5) E9(-4.5,8.5) E10(-3.5,8.5) E11(-2.5,8.5) E12(-1.5,8.5) E13(-0.5,8.5) E14(0.5,8.5) E15(1.5,8.5) E16(2.5,8.5) E17(3.5,8.5) E18(4.5,8.5) E19(5.5,8.5) E20(6.5,8.5) E21(7.5,8.5) E22(8.5,8.5) E23(9.5,8.5) E24(10.5,8.5) E25(11.5,8.5) E26(12.5,8.5) F1(-12.5,7.5) F2(-11.5,7.5) F3(-10.5,7.5) F4(-9.5,7.5) F5(-8.5,7.5) F6(-7.5,7.5) F7(-6.5,7.5) F8(-5.5,7.5) F9(-4.5,7.5) F10(-3.5,7.5) F11(-2.5,7.5) F12(-1.5,7.5) F13(-0.5,7.5) F14(0.5,7.5) F15(1.5,7.5) F16(2.5,7.5) F17(3.5,7.5) F18(4.5,7.5) F19(5.5,7.5) F20(6.5,7.5) F21(7.5,7.5) F22(8.5,7.5) F23(9.5,7.5) F24(10.5,7.5) F25(11.5,7.5) F26(12.5,7.5) G1(-12.5,6.5) G2(-11.5,6.5) G3(-10.5,6.5) G4(-9.5,6.5) G5(-8.5,6.5) G6(-7.5,6.5) G7(-6.5,6.5) G8(-5.5,6.5) G9(-4.5,6.5) G10(-3.5,6.5) G11(-2.5,6.5) G12(-1.5,6.5) G13(-0.5,6.5) G14(0.5,6.5) G15(1.5,6.5) G16(2.5,6.5) G17(3.5,6.5) G18(4.5,6.5) G19(5.5,6.5) G20(6.5,6.5) G21(7.5,6.5) G22(8.5,6.5) G23(9.5,6.5) G24(10.5,6.5) G25(11.5,6.5) G26(12.5,6.5) H1(-12.5,5.5) H2(-11.5,5.5) H3(-10.5,5.5) H4(-9.5,5.5) H5(-8.5,5.5) H6(-7.5,5.5) H7(-6.5,5.5) H8(-5.5,5.5) H9(-4.5,5.5) H10(-3.5,5.5) H11(-2.5,5.5) H12(-1.5,5.5) H13(-0.5,5.5) H14(0.5,5.5) H15(1.5,5.5) H16(2.5,5.5) H17(3.5,5.5) H18(4.5,5.5) H19(5.5,5.5) H20(6.5,5.5) H21(7.5,5.5) H22(8.5,5.5) H23(9.5,5.5) H24(10.5,5.5) H25(11.5,5.5) H26(12.5,5.5) J1(-12.5,4.5) J2(-11.5,4.5) J3(-10.5,4.5) J4(-9.5,4.5) J5(-8.5,4.5) J6(-7.5,4.5) J7(-6.5,4.5) J8(-5.5,4.5) J10(-3.5,4.5) J11(-2.5,4.5) J12(-1.5,4.5) J13(-0.5,4.5) J14(0.5,4.5) J15(1.5,4.5) J16(2.5,4.5) J17(3.5,4.5) J19(5.5,4.5) J20(6.5,4.5) J21(7.5,4.5) J22(8.5,4.5) J23(9.5,4.5) J24(10.5,4.5) J25(11.5,4.5) J26(12.5,4.5) K1(-12.5,3.5) K2(-11.5,3.5) K3(-10.5,3.5) K4(-9.5,3.5) K5(-8.5,3.5) K6(-7.5,3.5) K7(-6.5,3.5) K8(-5.5,3.5) K9(-4.5,3.5) K10(-3.5,3.5) K11(-2.5,3.5) K12(-1.5,3.5) K13(-0.5,3.5) K14(0.5,3.5) K15(1.5,3.5) K16(2.5,3.5) K17(3.5,3.5) K18(4.5,3.5) K19(5.5,3.5) K20(6.5,3.5) K21(7.5,3.5) K22(8.5,3.5) K23(9.5,3.5) K24(10.5,3.5) K25(11.5,3.5) K26(12.5,3.5) L1(-12.5,2.5) L2(-11.5,2.5) L3(-10.5,2.5) L4(-9.5,2.5) L5(-8.5,2.5) L6(-7.5,2.5) L7(-6.5,2.5) L8(-5.5,2.5) L9(-4.5,2.5) L10(-3.5,2.5) L11(-2.5,2.5) L12(-1.5,2.5) L13(-0.5,2.5) L14(0.5,2.5) L15(1.5,2.5) L16(2.5,2.5) L17(3.5,2.5) L18(4.5,2.5) L19(5.5,2.5) L20(6.5,2.5) L21(7.5,2.5) L22(8.5,2.5) L23(9.5,2.5) L24(10.5,2.5) L25(11.5,2.5) L26(12.5,2.5) M1(-12.5,1.5) M2(-11.5,1.5) M3(-10.5,1.5) M4(-9.5,1.5) M5(-8.5,1.5) M6(-7.5,1.5) M7(-6.5,1.5) M8(-5.5,1.5) M9(-4.5,1.5) M10(-3.5,1.5) M11(-2.5,1.5) M12(-1.5,1.5) M13(-0.5,1.5) M14(0.5,1.5) M15(1.5,1.5) M16(2.5,1.5) M17(3.5,1.5) M18(4.5,1.5) M19(5.5,1.5) M20(6.5,1.5) M21(7.5,1.5) M22(8.5,1.5) M23(9.5,1.5) M24(10.5,1.5) M25(11.5,1.5) M26(12.5,1.5) N1(-12.5,0.5) N2(-11.5,0.5) N3(-10.5,0.5) N4(-9.5,0.5) N5(-8.5,0.5) N6(-7.5,0.5) N7(-6.5,0.5) N8(-5.5,0.5) N9(-4.5,0.5) N10(-3.5,0.5) N11(-2.5,0.5) N12(-1.5,0.5) N13(-0.5,0.5) N14(0.5,0.5) N15(1.5,0.5) N16(2.5,0.5) N17(3.5,0.5) N18(4.5,0.5) N19(5.5,0.5) N20(6.5,0.5) N21(7.5,0.5) N22(8.5,0.5) N23(9.5,0.5) N24(10.5,0.5) N25(11.5,0.5) N26(12.5,0.5) P1(-12.5,-0.5) P2(-11.5,-0.5) P3(-10.5,-0.5) P4(-9.5,-0.5) P5(-8.5,-0.5) P6(-7.5,-0.5) P7(-6.5,-0.5) P8(-5.5,-0.5) P9(-4.5,-0.5) P10(-3.5,-0.5) P11(-2.5,-0.5) P12(-1.5,-0.5) P13(-0.5,-0.5) P14(0.5,-0.5) P15(1.5,-0.5) P16(2.5,-0.5) P17(3.5,-0.5) P18(4.5,-0.5) P19(5.5,-0.5) P20(6.5,-0.5) P21(7.5,-0.5) P22(8.5,-0.5) P23(9.5,-0.5) P24(10.5,-0.5) P25(11.5,-0.5) P26(12.5,-0.5) R1(-12.5,-1.5) R2(-11.5,-1.5) R3(-10.5,-1.5) R4(-9.5,-1.5) R5(-8.5,-1.5) R6(-7.5,-1.5) R7(-6.5,-1.5) R8(-5.5,-1.5) R9(-4.5,-1.5) R10(-3.5,-1.5) R11(-2.5,-1.5) R12(-1.5,-1.5) R13(-0.5,-1.5) R14(0.5,-1.5) R15(1.5,-1.5) R16(2.5,-1.5) R17(3.5,-1.5) R18(4.5,-1.5) R19(5.5,-1.5) R20(6.5,-1.5) R21(7.5,-1.5) R22(8.5,-1.5) R23(9.5,-1.5) R24(10.5,-1.5) R25(11.5,-1.5) R26(12.5,-1.5) T1(-12.5,-2.5) T2(-11.5,-2.5) T3(-10.5,-2.5) T4(-9.5,-2.5) T5(-8.5,-2.5) T6(-7.5,-2.5) T7(-6.5,-2.5) T8(-5.5,-2.5) T9(-4.5,-2.5) T10(-3.5,-2.5) T11(-2.5,-2.5) T12(-1.5,-2.5) T13(-0.5,-2.5) T14(0.5,-2.5) T15(1.5,-2.5) T16(2.5,-2.5) T17(3.5,-2.5) T18(4.5,-2.5) T19(5.5,-2.5) T20(6.5,-2.5) T21(7.5,-2.5) T22(8.5,-2.5) T23(9.5,-2.5) T24(10.5,-2.5) T25(11.5,-2.5) T26(12.5,-2.5) U1(-12.5,-3.5) U2(-11.5,-3.5) U3(-10.5,-3.5) U4(-9.5,-3.5) U5(-8.5,-3.5) U6(-7.5,-3.5) U7(-6.5,-3.5) U8(-5.5,-3.5) U9(-4.5,-3.5) U10(-3.5,-3.5) U11(-2.5,-3.5) U12(-1.5,-3.5) U13(-0.5,-3.5) U14(0.5,-3.5) U15(1.5,-3.5) U16(2.5,-3.5) U17(3.5,-3.5) U18(4.5,-3.5) U19(5.5,-3.5) U20(6.5,-3.5) U21(7.5,-3.5) U22(8.5,-3.5) U23(9.5,-3.5) U24(10.5,-3.5) U25(11.5,-3.5) U26(12.5,-3.5) V1(-12.5,-4.5) V2(-11.5,-4.5) V3(-10.5,-4.5) V4(-9.5,-4.5) V5(-8.5,-4.5) V6(-7.5,-4.5) V7(-6.5,-4.5) V8(-5.5,-4.5) V10(-3.5,-4.5) V11(-2.5,-4.5) V12(-1.5,-4.5) V13(-0.5,-4.5) V14(0.5,-4.5) V15(1.5,-4.5) V16(2.5,-4.5) V17(3.5,-4.5) V19(5.5,-4.5) V20(6.5,-4.5) V21(7.5,-4.5) V22(8.5,-4.5) V23(9.5,-4.5) V24(10.5,-4.5) V25(11.5,-4.5) V26(12.5,-4.5) W1(-12.5,-5.5) W2(-11.5,-5.5) W3(-10.5,-5.5) W4(-9.5,-5.5) W5(-8.5,-5.5) W6(-7.5,-5.5) W7(-6.5,-5.5) W8(-5.5,-5.5) W9(-4.5,-5.5) W10(-3.5,-5.5) W11(-2.5,-5.5) W12(-1.5,-5.5) W13(-0.5,-5.5) W14(0.5,-5.5) W15(1.5,-5.5) W16(2.5,-5.5) W17(3.5,-5.5) W18(4.5,-5.5) W19(5.5,-5.5) W20(6.5,-5.5) W21(7.5,-5.5) W22(8.5,-5.5) W23(9.5,-5.5) W24(10.5,-5.5) W25(11.5,-5.5) W26(12.5,-5.5) Y1(-12.5,-6.5) Y2(-11.5,-6.5) Y3(-10.5,-6.5) Y4(-9.5,-6.5) Y5(-8.5,-6.5) Y6(-7.5,-6.5) Y7(-6.5,-6.5) Y8(-5.5,-6.5) Y9(-4.5,-6.5) Y10(-3.5,-6.5) Y11(-2.5,-6.5) Y12(-1.5,-6.5) Y13(-0.5,-6.5) Y14(0.5,-6.5) Y15(1.5,-6.5) Y16(2.5,-6.5) Y17(3.5,-6.5) Y18(4.5,-6.5) Y19(5.5,-6.5) Y20(6.5,-6.5) Y21(7.5,-6.5) Y22(8.5,-6.5) Y23(9.5,-6.5) Y24(10.5,-6.5) Y25(11.5,-6.5) Y26(12.5,-6.5)
  silkscreen extent -14.27,-13.5 13.5,13.5, body extent -13.5,-13.61 13.6,13.46, height 2.92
